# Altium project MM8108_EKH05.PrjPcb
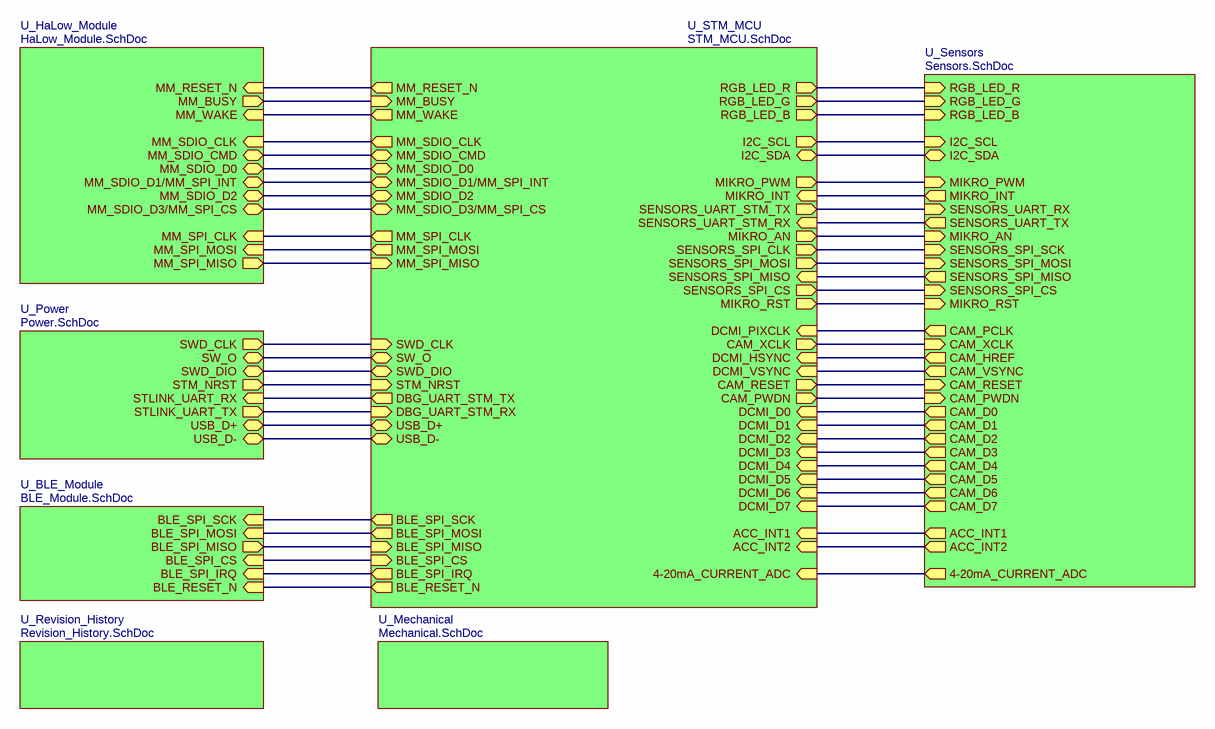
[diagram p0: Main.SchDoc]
PCBRev: 2.0; Rev: 2.1; DrawnBy: J. Garnier; Checked: Matthew Jay; Approved: Chad O'Neill
8 sheets, 188 parts. Net scope: hierarchical (ports join the sheet entries above them; power ports are global).
Board file: MM8108_EKH05.PcbDoc
Sheets:
  Main.SchDoc
    U_Power = Power.SchDoc
    U_STM_MCU = STM_MCU.SchDoc
    U_Sensors = Sensors.SchDoc
    U_BLE_Module = BLE_Module.SchDoc
    U_HaLow_Module = HaLow_Module.SchDoc
    U_Revision_History = Revision_History.SchDoc
    U_Mechanical = Mechanical.SchDoc

## Sheet Main.SchDoc: Top Level
size A4; ApprovedBy: Chad O'Neill; CheckedBy: Matthew Jay; Author: J. Garnier; DrawnBy: J. Garnier; Revision: 2.1; SheetNumber: 1; SheetTotal: 8

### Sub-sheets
U_BLE_Module = BLE_Module.SchDoc: BLE_RESET_N (in), BLE_SPI_IRQ (in), BLE_SPI_CS (in), BLE_SPI_SCK (in), BLE_SPI_MISO (out), BLE_SPI_MOSI (in)
U_HaLow_Module = HaLow_Module.SchDoc: MM_BUSY (out), MM_SDIO_D2 (bidir), MM_SDIO_D0 (bidir), MM_SDIO_CMD (bidir), MM_SDIO_CLK (in), MM_RESET_N (in), MM_WAKE (in), MM_SPI_MISO (out), MM_SPI_MOSI (in), MM_SPI_CLK (in), MM_SDIO_D1/MM_SPI_INT (bidir), MM_SDIO_D3/MM_SPI_CS (bidir)
U_Mechanical = Mechanical.SchDoc: no entries
U_Power = Power.SchDoc: SWD_CLK (out), SWD_DIO (bidir), STLINK_UART_RX (in), STLINK_UART_TX (out), STM_NRST (out), SW_O (bidir), USB_D+ (bidir), USB_D- (bidir)
U_Revision_History = Revision_History.SchDoc: no entries
U_Sensors = Sensors.SchDoc: ACC_INT1 (out), ACC_INT2 (out), RGB_LED_B (in), RGB_LED_G (in), RGB_LED_R (in), I2C_SCL (in), I2C_SDA (bidir), CAM_HREF (out), CAM_XCLK (in), CAM_D6 (out), CAM_D4 (out), CAM_D2 (out), CAM_D0 (out), CAM_D7 (out), CAM_D5 (out), CAM_D3 (out), CAM_D1 (out), CAM_PWDN (in), CAM_RESET (in), CAM_PCLK (out), CAM_VSYNC (out), MIKRO_INT (out), SENSORS_UART_RX (in), MIKRO_AN (in), SENSORS_SPI_CS (in), SENSORS_SPI_SCK (in), SENSORS_SPI_MISO (out), SENSORS_SPI_MOSI (in), SENSORS_UART_TX (out), MIKRO_PWM (in), MIKRO_RST (in), 4-20mA_CURRENT_ADC (out)
U_STM_MCU = STM_MCU.SchDoc: MM_RESET_N (out), SWD_DIO (bidir), SWD_CLK (in), SENSORS_SPI_MOSI (out), RGB_LED_G (out), RGB_LED_R (out), MM_SPI_CLK (out), RGB_LED_B (out), MM_SDIO_D0 (bidir), MM_BUSY (in), MM_SPI_MISO (in), MM_SPI_MOSI (out), MM_SDIO_CLK (out), MM_SDIO_CMD (bidir), MM_SDIO_D2 (bidir), DCMI_D5 (in), I2C_SCL (out), I2C_SDA (bidir), DCMI_D4 (in), DCMI_D6 (in), DCMI_D7 (in), DCMI_D3 (in), DCMI_D2 (in), DCMI_D1 (in), DCMI_D0 (in), DCMI_PIXCLK (in), DCMI_HSYNC (in), CAM_RESET (out), CAM_PWDN (out), ACC_INT1 (in), ACC_INT2 (in), DBG_UART_STM_RX (in), DBG_UART_STM_TX (out), BLE_RESET_N (out), SENSORS_UART_STM_RX (in), SENSORS_UART_STM_TX (out), DCMI_VSYNC (in), MM_WAKE (out), CAM_XCLK (out), SENSORS_SPI_MISO (in), SENSORS_SPI_CLK (out), SENSORS_SPI_CS (out), MIKRO_INT (in), MIKRO_AN (out), MIKRO_PWM (out), MIKRO_RST (out), 4-20mA_CURRENT_ADC (in), STM_NRST (in), SW_O (bidir), USB_D+ (bidir), USB_D- (bidir), MM_SDIO_D1/MM_SPI_INT (bidir), MM_SDIO_D3/MM_SPI_CS (bidir), BLE_SPI_SCK (out), BLE_SPI_CS (in), BLE_SPI_IRQ (out), BLE_SPI_MISO (in), BLE_SPI_MOSI (out)

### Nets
ACC_INT1: sheet U_STM_MCU/ACC_INT1, sheet U_Sensors/ACC_INT1
ACC_INT2: sheet U_STM_MCU/ACC_INT2, sheet U_Sensors/ACC_INT2
BLE_RESET_N: sheet U_STM_MCU/BLE_RESET_N, sheet U_BLE_Module/BLE_RESET_N
BLE_SPI_CS: sheet U_STM_MCU/BLE_SPI_CS, sheet U_BLE_Module/BLE_SPI_CS
BLE_SPI_IRQ: sheet U_STM_MCU/BLE_SPI_IRQ, sheet U_BLE_Module/BLE_SPI_IRQ
BLE_SPI_MISO: sheet U_STM_MCU/BLE_SPI_MISO, sheet U_BLE_Module/BLE_SPI_MISO
BLE_SPI_MOSI: sheet U_STM_MCU/BLE_SPI_MOSI, sheet U_BLE_Module/BLE_SPI_MOSI
BLE_SPI_SCK: sheet U_STM_MCU/BLE_SPI_SCK, sheet U_BLE_Module/BLE_SPI_SCK
CAM_PWDN: sheet U_STM_MCU/CAM_PWDN, sheet U_Sensors/CAM_PWDN
CAM_RESET: sheet U_STM_MCU/CAM_RESET, sheet U_Sensors/CAM_RESET
CAM_XCLK: sheet U_STM_MCU/CAM_XCLK, sheet U_Sensors/CAM_XCLK
DBG_UART_STM_RX: sheet U_Power/STLINK_UART_TX, sheet U_STM_MCU/DBG_UART_STM_RX
DBG_UART_STM_TX: sheet U_Power/STLINK_UART_RX, sheet U_STM_MCU/DBG_UART_STM_TX
DCMI_D0: sheet U_STM_MCU/DCMI_D0, sheet U_Sensors/CAM_D0
DCMI_D1: sheet U_STM_MCU/DCMI_D1, sheet U_Sensors/CAM_D1
DCMI_D2: sheet U_STM_MCU/DCMI_D2, sheet U_Sensors/CAM_D2
DCMI_D3: sheet U_STM_MCU/DCMI_D3, sheet U_Sensors/CAM_D3
DCMI_D4: sheet U_STM_MCU/DCMI_D4, sheet U_Sensors/CAM_D4
DCMI_D5: sheet U_STM_MCU/DCMI_D5, sheet U_Sensors/CAM_D5
DCMI_D6: sheet U_STM_MCU/DCMI_D6, sheet U_Sensors/CAM_D6
DCMI_D7: sheet U_STM_MCU/DCMI_D7, sheet U_Sensors/CAM_D7
DCMI_HSYNC: sheet U_STM_MCU/DCMI_HSYNC, sheet U_Sensors/CAM_HREF
DCMI_PIXCLK: sheet U_STM_MCU/DCMI_PIXCLK, sheet U_Sensors/CAM_PCLK
DCMI_VSYNC: sheet U_STM_MCU/DCMI_VSYNC, sheet U_Sensors/CAM_VSYNC
I2C_SCL: sheet U_STM_MCU/I2C_SCL, sheet U_Sensors/I2C_SCL
I2C_SDA: sheet U_STM_MCU/I2C_SDA, sheet U_Sensors/I2C_SDA
MIKRO_AN: sheet U_STM_MCU/MIKRO_AN, sheet U_Sensors/MIKRO_AN
MIKRO_INT: sheet U_STM_MCU/MIKRO_INT, sheet U_Sensors/MIKRO_INT
MIKRO_PWM: sheet U_STM_MCU/MIKRO_PWM, sheet U_Sensors/MIKRO_PWM
MIKRO_RST: sheet U_STM_MCU/MIKRO_RST, sheet U_Sensors/MIKRO_RST
MM_BUSY: sheet U_STM_MCU/MM_BUSY, sheet U_HaLow_Module/MM_BUSY
MM_RESET_N: sheet U_STM_MCU/MM_RESET_N, sheet U_HaLow_Module/MM_RESET_N
MM_SDIO_D1: sheet U_STM_MCU/MM_SDIO_D1/MM_SPI_INT, sheet U_HaLow_Module/MM_SDIO_D1/MM_SPI_INT
MM_SDIO_D2: sheet U_STM_MCU/MM_SDIO_D2, sheet U_HaLow_Module/MM_SDIO_D2
MM_SDIO_D3: sheet U_STM_MCU/MM_SDIO_D3/MM_SPI_CS, sheet U_HaLow_Module/MM_SDIO_D3/MM_SPI_CS
MM_WAKE: sheet U_STM_MCU/MM_WAKE, sheet U_HaLow_Module/MM_WAKE
PD11: sheet U_STM_MCU/4-20mA_CURRENT_ADC, sheet U_Sensors/4-20mA_CURRENT_ADC
SDMMC2_CLK: sheet U_STM_MCU/MM_SDIO_CLK, sheet U_HaLow_Module/MM_SDIO_CLK
SDMMC2_CMD: sheet U_STM_MCU/MM_SDIO_CMD, sheet U_HaLow_Module/MM_SDIO_CMD
SDMMC2_D0: sheet U_STM_MCU/MM_SDIO_D0, sheet U_HaLow_Module/MM_SDIO_D0
SENSORS_SPI_CLK: sheet U_STM_MCU/SENSORS_SPI_CLK, sheet U_Sensors/SENSORS_SPI_SCK
SENSORS_SPI_CS: sheet U_STM_MCU/SENSORS_SPI_CS, sheet U_Sensors/SENSORS_SPI_CS
SENSORS_SPI_MISO: sheet U_STM_MCU/SENSORS_SPI_MISO, sheet U_Sensors/SENSORS_SPI_MISO
SENSORS_SPI_MOSI: sheet U_STM_MCU/SENSORS_SPI_MOSI, sheet U_Sensors/SENSORS_SPI_MOSI
SENSORS_UART_RX: sheet U_STM_MCU/SENSORS_UART_STM_TX, sheet U_Sensors/SENSORS_UART_RX
SENSORS_UART_TX: sheet U_STM_MCU/SENSORS_UART_STM_RX, sheet U_Sensors/SENSORS_UART_TX
STM_NRST: sheet U_Power/STM_NRST, sheet U_STM_MCU/STM_NRST
STM_SPI2_CLK: sheet U_STM_MCU/MM_SPI_CLK, sheet U_HaLow_Module/MM_SPI_CLK
STM_SPI2_MISO: sheet U_STM_MCU/MM_SPI_MISO, sheet U_HaLow_Module/MM_SPI_MISO
STM_SPI2_MOSI: sheet U_STM_MCU/MM_SPI_MOSI, sheet U_HaLow_Module/MM_SPI_MOSI
SWD_CLK: sheet U_Power/SWD_CLK, sheet U_STM_MCU/SWD_CLK
SWD_DIO: sheet U_Power/SWD_DIO, sheet U_STM_MCU/SWD_DIO
TIM4_CH1: sheet U_STM_MCU/RGB_LED_R, sheet U_Sensors/RGB_LED_R
TIM4_CH2: sheet U_STM_MCU/RGB_LED_G, sheet U_Sensors/RGB_LED_G
TIM4_CH3: sheet U_STM_MCU/RGB_LED_B, sheet U_Sensors/RGB_LED_B
USBC_N: sheet U_Power/USB_D-, sheet U_STM_MCU/USB_D-
USBC_P: sheet U_Power/USB_D+, sheet U_STM_MCU/USB_D+
NetH16_5: sheet U_Power/SW_O, sheet U_STM_MCU/SW_O

## Sheet Power.SchDoc: Power
size A3; ApprovedBy: Chad O'Neill; CheckedBy: Matthew Jay; Author: J. Garnier; DrawnBy: J. Garnier; Revision: 2.1; SheetNumber: 6; SheetTotal: 8
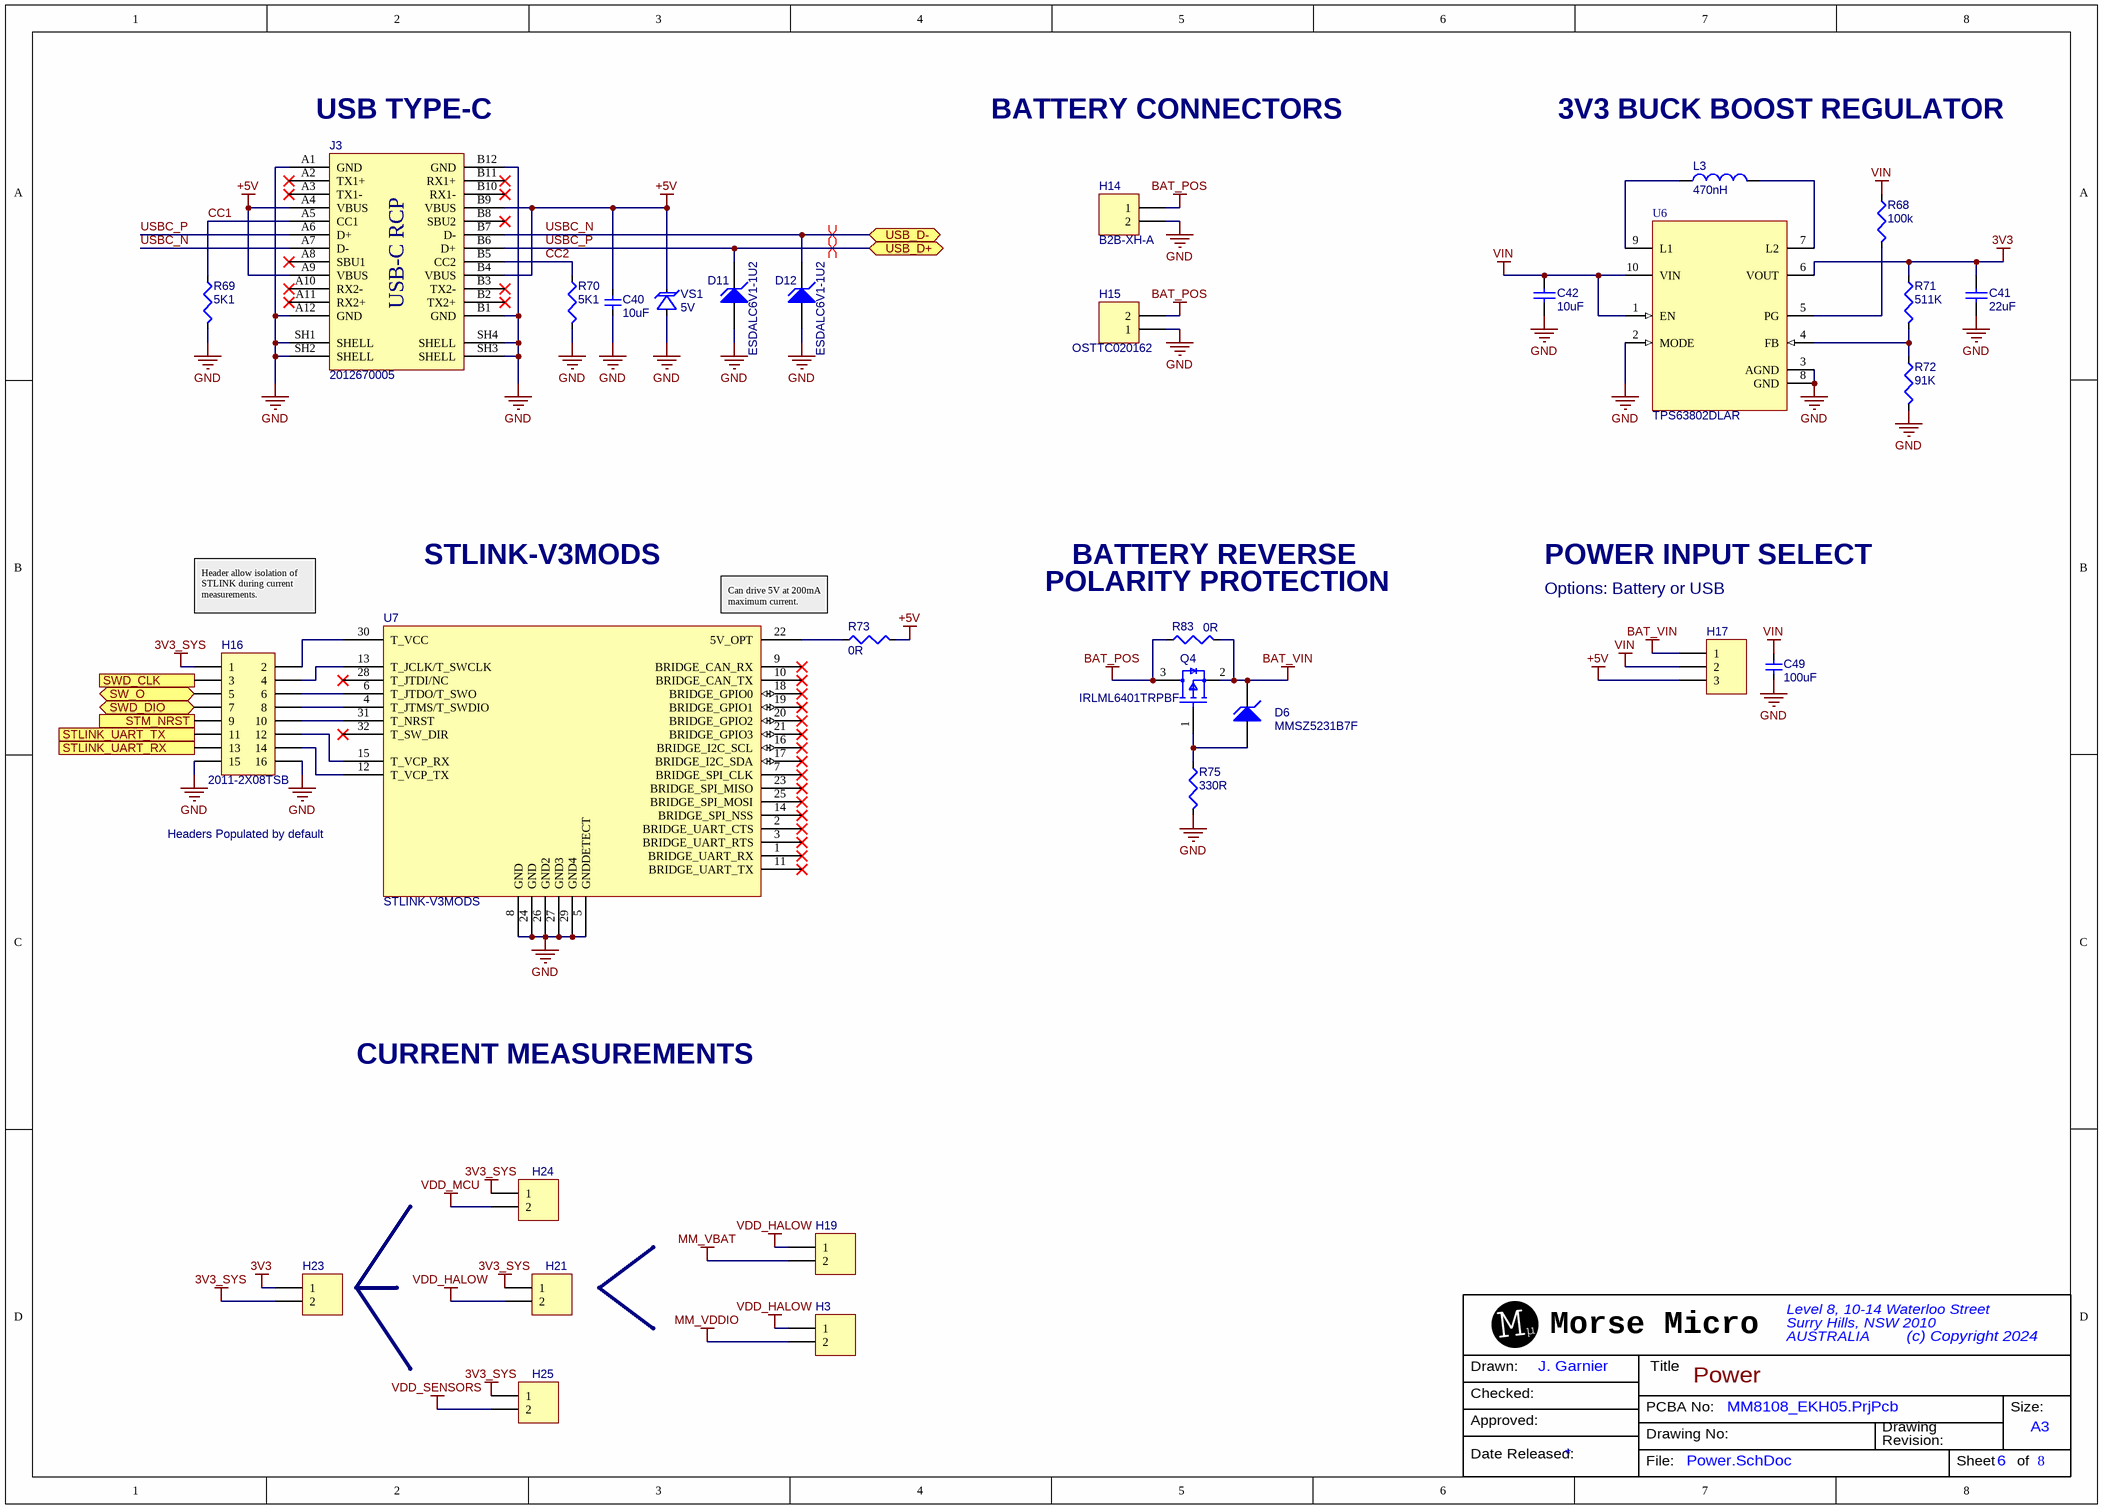
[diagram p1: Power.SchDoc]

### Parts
C40  value 10uF  [CAPC1608X06N]  (hidden comment: GRM188R61E106MA73J)
C41  value 22uF  [0603_cap]  (hidden comment: GRM188R60J226MEA0D)
C42  value 10uF  [0603_cap]  (hidden comment: GRM155R60J106ME05)
C49  value 100uF  [CAPC3225X20N]  (hidden comment: CL32A107MPVNNNE)
D6  MMSZ5231B7F  [SOD-123FL]
D11  ESDALC6V1-1U2  [0201_DIODE]
D12  ESDALC6V1-1U2  [0201_DIODE]
H3  2011-1X02G00SB-1  [HDR1X2]  (value not drawn)
H14  B2B-XH-A  [B2B-XH-A]
H15  OSTTC020162  [SCREW_TERM_2WAY_5MM]
H16  2011-2X08TSB  [HDR2X8 Short Gold]
H17  2011-1X03G00SB  [HDR1X3]  (value not drawn)
H19  2011-1X02G00SB-1  [HDR1X2]  (value not drawn)
H21  2011-1X02G00SB-1  [HDR1X2]  (value not drawn)
H23  2011-1X02G00SB-1  [HDR1X2]  (value not drawn)
H24  2011-1X02G00SB-1  [HDR1X2]  (value not drawn)
H25  2011-1X02G00SB-1  [HDR1X2]  (value not drawn)
J3  2012670005  [USB-C_RCP]
L3  value 470nH  [INDC2520X120N]  (hidden comment: DFE252012PR47MP2)
Q4  IRLML6401TRPBF  [FP-SOT23-IPC_A]
R68  value 100k  [RESC1005X04N]  (hidden comment: RC0402FR-07100KL)
R69  value 5K1  [RESC1005X04N]  (hidden comment: MCR01MZPF5101)
R70  value 5K1  [RESC1005X04N]  (hidden comment: MCR01MZPF5101)
R71  value 511K  [0402_res]  (hidden comment: RES0262)
R72  value 91K  [0402_res]  (hidden comment: RES0263)
R73  value 0R  [RESC1608X06N]  (hidden comment: RC0603JR-070RL)
R75  value 330R  [RESC1005X04N]  (hidden comment: RC0402FR-07330RL)
R83  value 0R  [RESC1608X06N]  (hidden comment: RC0603JR-070RL)
U6  TPS63802DLAR  [TPS63802DLAR]
U7  STLINK-V3MODS  [STLINK-V3MODS]
VS1  value 5V  [SOD-523]  (hidden comment: ESD5Z5.0T1G)

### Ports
STLINK_UART_RX (in, see Main[2B]), STLINK_UART_TX (out, see Main[2B]), STM_NRST (out, see Main[2B], STM_MCU[1B]), SW_O (bidir, see Main[2B], STM_MCU[4C]), SWD_CLK (out, see Main[2B], STM_MCU[5B]), SWD_DIO (bidir, see Main[2B], STM_MCU[5B]), USB_D+ (bidir, see Main[2B], STM_MCU[5B]), USB_D- (bidir, see Main[2B], STM_MCU[5B])

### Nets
3V3: C41.2 H23.1 R71.1 U6.6(VOUT)
3V3_SYS: H16.1 H21.1 H23.2 H24.1 H25.1
+5V: C40.1 H17.3 J3.A4(VBUS) J3.A9(VBUS) J3.B4(VBUS) J3.B9(VBUS) R73.2 VS1.K
BAT_POS: H14.1 H15.2 Q4.3(D) R83.1
BAT_VIN: D6.K H17.1 Q4.2(S) R83.2
GND: C40.2 C41.1 C42.1 C49.2 D11.A D12.A H14.2 H15.1 H16.15 H16.16 J3.A1(GND) J3.A12(GND) J3.B1(GND) J3.B12(GND) J3.SH1(SHELL) J3.SH2(SHELL) J3.SH3(SHELL) J3.SH4(SHELL) R69.2 R70.2 R72.2 R75.2 U6.2(MODE) U6.3(AGND) U6.8(GND) U7.5(GNDDETECT) U7.8(GND) U7.24(GND) U7.26(GND2) U7.27(GND3) U7.29(GND4) VS1.A
MM_VBAT: H19.2
MM_VDDIO: H3.2
VDD_HALOW: H3.1 H19.1 H21.2
VDD_MCU: H24.2
VDD_SENSORS: H25.2
VIN: C42.2 C49.1 H17.2 R68.1 U6.1(EN) U6.10(VIN)
CC1: J3.A5(CC1) R69.1
CC2: J3.B5(CC2) R70.1
DBG_UART_STM_RX: H16.11 ; port STLINK_UART_TX
DBG_UART_STM_TX: H16.13 ; port STLINK_UART_RX
STM_NRST: H16.9 ; port STM_NRST
SWD_CLK: H16.3 ; port SWD_CLK
SWD_DIO: H16.7 ; port SWD_DIO
USBC_N: D12.K J3.A7(D-) J3.B7(D-) ; port USB_D-
USBC_P: D11.K J3.A6(D+) J3.B6(D+) ; port USB_D+
NetD6_A: D6.A Q4.1(G) R75.1
NetH16_2: H16.2 U7.30(T_VCC)
NetH16_4: H16.4 U7.13(T_JCLK/T_SWCLK)
NetH16_5: H16.5 ; port SW_O
NetH16_6: H16.6 U7.6(T_JTDO/T_SWO)
NetH16_8: H16.8 U7.4(T_JTMS/T_SWDIO)
NetH16_10: H16.10 U7.31(T_NRST)
NetH16_12: H16.12 U7.15(T_VCP_RX)
NetH16_14: H16.14 U7.12(T_VCP_TX)
NetL3_1: L3.1 U6.9(L1)
NetL3_2: L3.2 U6.7(L2)
NetR68_2: R68.2 U6.5(PG)
NetR71_2: R71.2 R72.1 U6.4(FB)
NetR73_1: R73.1 U7.22(5V_OPT)

Not connected (* = marked no-connect by the designer): J3 A2(TX1+)* A3(TX1-)* A8(SBU1)* A10(RX2-)* A11(RX2+)* B2(TX2+)* B3(TX2-)* B8(SBU2)* B10(RX1-)* B11(RX1+)*; U7 1(BRIDGE_UART_RX)* 2(BRIDGE_UART_CTS)* 3(BRIDGE_UART_RTS)* 7(BRIDGE_SPI_CLK)* 9(BRIDGE_CAN_RX)* 10(BRIDGE_CAN_TX)* 11(BRIDGE_UART_TX)* 14(BRIDGE_SPI_NSS)* 16(BRIDGE_I2C_SCL)* 17(BRIDGE_I2C_SDA)* 18(BRIDGE_GPIO0)* 19(BRIDGE_GPIO1)* 20(BRIDGE_GPIO2)* 21(BRIDGE_GPIO3)* 23(BRIDGE_SPI_MISO)* 25(BRIDGE_SPI_MOSI)* 28(T_JTDI/NC)* 32(T_SW_DIR)*

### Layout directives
differential pair: USBC_N, USBC_P

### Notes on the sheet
- (near J3) USB TYPE-C
- BATTERY CONNECTORS
- 3V3 BUCK BOOST REGULATOR
- STLINK-V3MODS
- BATTERY REVERSE
- POWER INPUT SELECT
- Header allow isolation of STLINK during current measurements.
- Can drive 5V at 200mA maximum current.
- (near R83) POLARITY PROTECTION
- Options: Battery or USB
- Headers Populated by default
- CURRENT MEASUREMENTS

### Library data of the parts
C40 = CAP0197-5: CAP CER 10UF 25V ±20% X5R 0603; Generic Allowed: Yes; Subtype: Ceramic
C41 = CAP0243-1: Multilayer Ceramic Capacitor, 22 uF, 6.3 V, ± 20%, X5R, 0603 [1608 Metric]; Voltage Rating (DC): 6.3V
C42 = CAP0246-2: Ceramic Capacitor, Multilayer, Ceramic, 6.3V, 20% +Tol, 20% -Tol, X5R, 15% TC, 10uF, Surface Mount, 0402
C49 = CAP0047-3: CAP CER 100UF 10V ±20% X5R 1210; Generic Allowed: Yes; Subtype: Ceramic
D6 = DIO0072-1: DIODE ZENER 5.1V 500MW SOD-123
D11 D12 = DIO0043-4: TVS DIODE 3VWM ST020; Power: 20W; Generic Allowed: No; Voltage: 3V
H3 H19 H21 H23-H25 = HDR0006-2: Conn Straight Header 2x1 0.100" 2 POS; Generic Allowed: Yes
H14 = HDR0117-1: Board Connector, 2 Contact(s), 1 Row(s), Male, Straight, Solder Terminal,
H15 = JCK0020-1: CONN TERM BLOCK 5MM 2POS; Generic Allowed: Yes
H16 = HDR0116-2
H17 = HDR0008-2: Conn Straight Header 3x1 0.100" 3 POS; Generic Allowed: Yes
J3 = JCK0027-1: CONN RCP USB3.1 TYPEC 24P SMD RA; Generic Allowed: Yes
L3 = IND0139-3: Generic Allowed: NO; Current: 4; DC Resistance: 27mOhm
Q4 = TSR0020-1: Small Signal Field-Effect Transistor; Transistor Element Material: SILICON; Drain-source On Resistance-Max: 50mR; Power Dissipation-Max (Abs): 1.3W; Drain Current-Max (Abs) (ID): 4.3A; Polarity/Channel Type: P-CHANNEL; Number of Elements: 1; DS Breakdown Voltage-Min: 12V; Transistor Application: SWITCHING; FET Technology: METAL-OXIDE SEMICONDUCTOR; Qualification Status: Not Qualified; Additional Feature: HIGH RELIABILITY; Operating Mode: ENHANCEMENT MODE; Avalanche Energy Rating (Eas): 33mJ; Pulsed Drain Current-Max (IDM): 34A; Package Body Material: Plastic; Time @ Peak Reflow Temperature-Max (s): 30s
R68 = RES0044-8: RES SMD 100K OHM ±1% 1/16W 0402; Generic Allowed: Yes
R69 R70 = RES0094-8: RES SMD 5K1 OHM ±1% 1/16W 0402; Generic Allowed: Yes
R71 = RES0254-2: RES 511K OHM 1% 1/16W 0402; Manufacturer 1: YAGEO; Manufacturer Part Number 1: RC0402FR-07511KL; Subtype: Thick Film; Generic Allowed: Yes
R72 = RES0255-2: RES 91K OHM 1% 1/16W 0402; Manufacturer Part Number 1: RC0402FR-0791KL; Manufacturer 1: YAGEO; Generic Allowed: Yes; Subtype: Thick Film
R73 R83 = RES0119-6: RES SMD 0R OHM ±5% 1/10W 0603; Generic Allowed: Yes
R75 = RES0025-8: RES SMD 330R OHM ±1% 1/16W 0402; Generic Allowed: Yes
U6 = ICT0222-6: Generic Allowed: No
U7 = MOD0018-3
VS1 = DIO0073-1: TVS Diode,5V@9.4Amp, SOD-523 SMD; Current: 9.4A

## Sheet STM_MCU.SchDoc: STM_MCU
size A3; ApprovedBy: Chad O'Neill; CheckedBy: Matthew Jay; Author: J. Garnier; DrawnBy: J. Garnier; Revision: 2.1; SheetNumber: 2; SheetTotal: 8
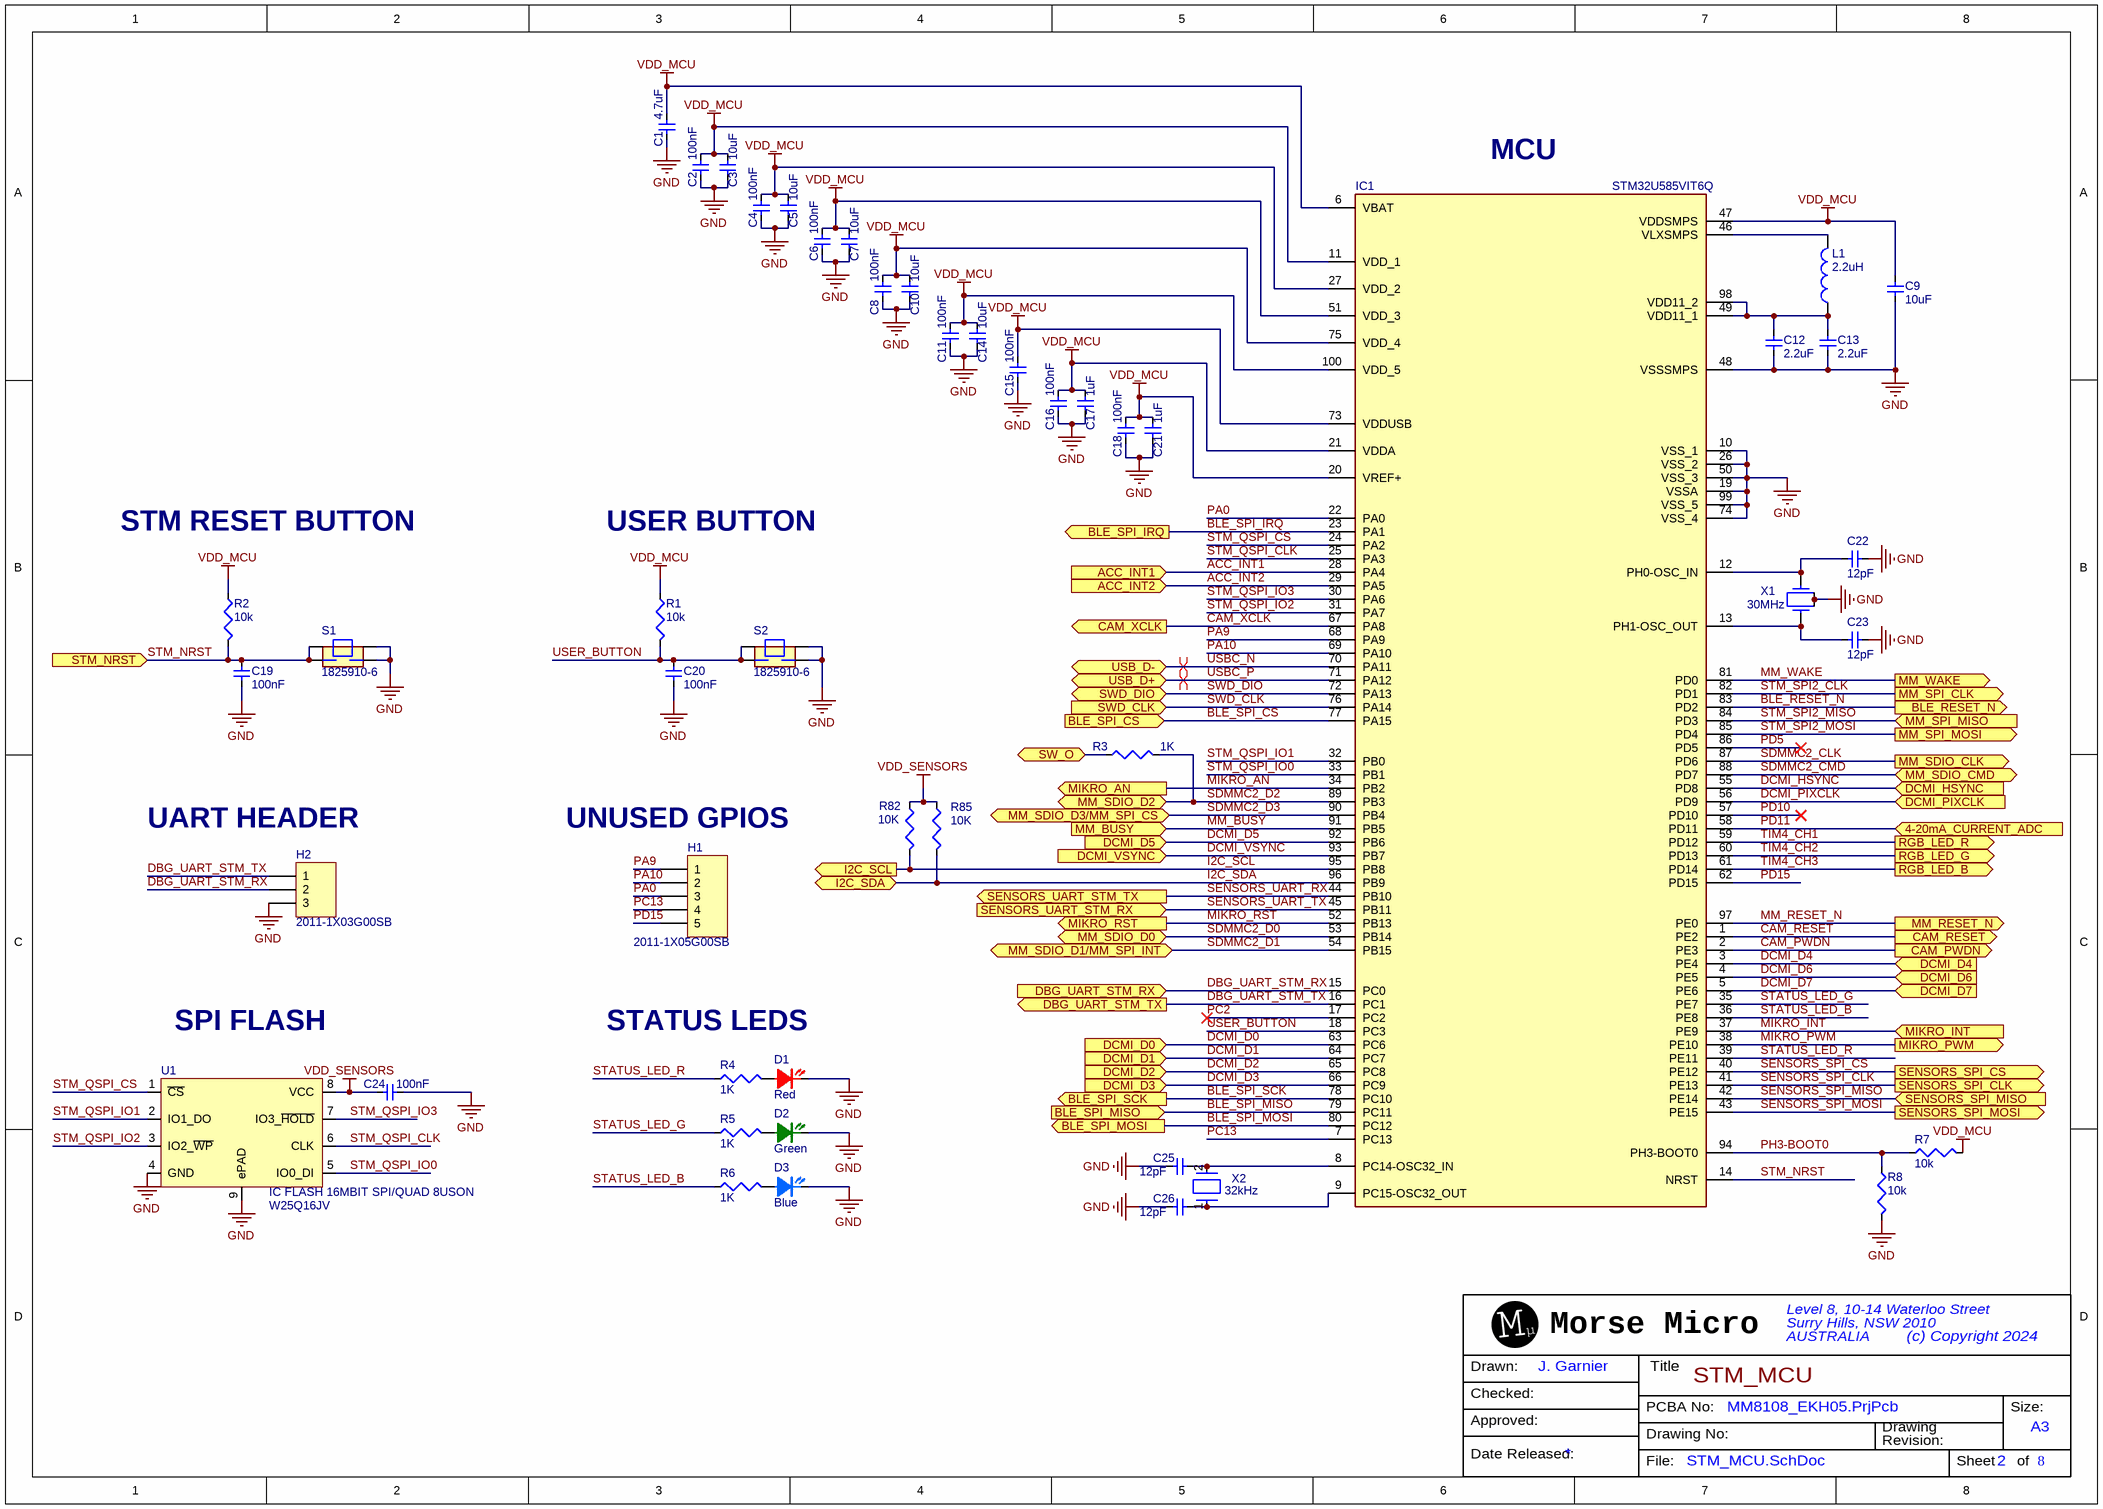
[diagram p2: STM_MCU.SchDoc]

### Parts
C1  value 4.7uF  [0402_cap]  (hidden comment: GRM155R61A475MEAAD)
C2  value 100nF  [0402_cap]  (hidden comment: C1005X7R1H104K050BE)
C3  value 10uF  [0402_cap]  (hidden comment: CL05A106MP8NUB8)
C4  value 100nF  [0402_cap]  (hidden comment: C1005X7R1H104K050BE)
C5  value 10uF  [0402_cap]  (hidden comment: CL05A106MP8NUB8)
C6  value 100nF  [0402_cap]  (hidden comment: C1005X7R1H104K050BE)
C7  value 10uF  [0402_cap]  (hidden comment: CL05A106MP8NUB8)
C8  value 100nF  [0402_cap]  (hidden comment: C1005X7R1H104K050BE)
C9  value 10uF  [0402_cap]  (hidden comment: CL05A106MP8NUB8)
C10  value 10uF  [0402_cap]  (hidden comment: CL05A106MP8NUB8)
C11  value 100nF  [0402_cap]  (hidden comment: C1005X7R1H104K050BE)
C12  value 2.2uF  [CAPC1005X06N]  (hidden comment: GRM155R61E225ME15D)
C13  value 2.2uF  [CAPC1005X06N]  (hidden comment: GRM155R61E225ME15D)
C14  value 10uF  [0402_cap]  (hidden comment: CL05A106MP8NUB8)
C15  value 100nF  [0402_cap]  (hidden comment: C1005X7R1H104K050BE)
C16  value 100nF  [0402_cap]  (hidden comment: C1005X7R1H104K050BE)
C17  value 1uF  [CAPC1005X06N]  (hidden comment: CL05A105KA5NQNC)
C18  value 100nF  [0402_cap]  (hidden comment: C1005X7R1H104K050BE)
C19  value 100nF  [CAPC1005X06N]  (hidden comment: LMK105BJ104KV-F)
C20  value 100nF  [CAPC1005X06N]  (hidden comment: LMK105BJ104KV-F)
C21  value 1uF  [CAPC1005X06N]  (hidden comment: CL05A105KA5NQNC)
C22  value 12pF  [CAPC0603X03N]  (hidden comment: GRM0335C1E120JA01D)
C23  value 12pF  [CAPC0603X03N]  (hidden comment: GRM0335C1E120JA01D)
C24  value 100nF  [CAPC0603X03N]  (hidden comment: CL03A104KQ3NNNC)
C25  value 12pF  [CAPC0603X03N]  (hidden comment: GRM0335C1E120JA01D)
C26  value 12pF  [CAPC0603X03N]  (hidden comment: GRM0335C1E120JA01D)
D1  value Red  [LED_0805_RED]  (hidden comment: LTST-C170KRKT)
D2  value Green  [LED_0805_GREEN]  (hidden comment: LTST-C170KGKT)
D3  value Blue  [LED_0805_BLUE]  (hidden comment: LTST-C170TBKT)
H1  2011-1X05G00SB  [HDR1X5 - Short Gold]
H2  2011-1X03G00SB  [HDR1X3]
IC1  STM32U585VIT6Q  [STM32U585VIT6]
L1  value 2.2uH  [INDC1608X10N]  (hidden comment: ASMPH-0603-2R2M-T)
R1  value 10k  [RESC1005X04N]  (hidden comment: MCR01MZPF1002)
R2  value 10k  [RESC1005X04N]  (hidden comment: MCR01MZPF1002)
R3  value 1K  [RESC1005X04N]  (hidden comment: ERJ-2RKF1001X)
R4  value 1K  [RESC1005X04N]  (hidden comment: ERJ-2RKF1001X)
R5  value 1K  [RESC1005X04N]  (hidden comment: ERJ-2RKF1001X)
R6  value 1K  [RESC1005X04N]  (hidden comment: ERJ-2RKF1001X)
R7  value 10k  [RESC1005X04N]  (hidden comment: MCR01MZPF1002)
R8  value 10k  [RESC1005X04N]  (hidden comment: MCR01MZPF1002)
R82  value 10K  [0402_res]  (hidden comment: ERJ-2RKF1002X)
R85  value 10K  [0402_res]  (hidden comment: ERJ-2RKF1002X)
S1  1825910-6  [TL1105]
S2  1825910-6  [TL1105]
U1  IC FLASH 16MBIT SPI/QUAD 8USON  value W25Q16JV  [USON8P20X30X6]
X1  value 30MHz  [XTAL_SMD_2016]  (hidden comment: ECS-300-10-37-CKM-TR)
X2  value 32kHz  [FP-ABS06-MFG]  (hidden comment: ABS06-107-32.768KHZ-T)

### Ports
4-20mA_CURRENT_ADC (in, see Main[3C], Sensors[7A]), ACC_INT1 (in, see Main[3C], Sensors[1D]), ACC_INT2 (in, see Main[3C], Sensors[1D]), BLE_RESET_N (out, see Main[2C], BLE_Module[2B]), BLE_SPI_CS (in, see Main[2C], BLE_Module[4B]), BLE_SPI_IRQ (out, see Main[2C], BLE_Module[4B]), BLE_SPI_MISO (in, see Main[2C], BLE_Module[4B]), BLE_SPI_MOSI (out, see Main[2C], BLE_Module[4B]), BLE_SPI_SCK (out, see Main[2C], BLE_Module[4A]), CAM_PWDN (out, see Main[3B], Sensors[7B]), CAM_RESET (out, see Main[3B], Sensors[5B]), CAM_XCLK (out, see Main[3B], Sensors[7B]), DBG_UART_STM_RX (in, see Main[2B]), DBG_UART_STM_TX (out, see Main[2B]), DCMI_D0 (in, see Main[3B]), DCMI_D1 (in, see Main[3B]), DCMI_D2 (in, see Main[3B]), DCMI_D3 (in, see Main[3C]), DCMI_D4 (in, see Main[3C]), DCMI_D5 (in, see Main[3C]), DCMI_D6 (in, see Main[3C]), DCMI_D7 (in, see Main[3C]), DCMI_HSYNC (in, see Main[3B]), DCMI_PIXCLK (in, see Main[3B]), DCMI_VSYNC (in, see Main[3B]), I2C_SCL (out, see Main[3A], Sensors[4A]), I2C_SDA (bidir, see Main[3A], Sensors[4A]), MIKRO_AN (out, see Main[3B], Sensors[2B]), MIKRO_INT (in, see Main[3B], Sensors[4B]), MIKRO_PWM (out, see Main[3A], Sensors[4B]), MIKRO_RST (out, see Main[3B], Sensors[2B]), MM_BUSY (in, see Main[2A], HaLow_Module[3A]), MM_RESET_N (out, see Main[2A], HaLow_Module[2B]), MM_SDIO_CLK (out, see Main[2A], HaLow_Module[2C]), MM_SDIO_CMD (bidir, see Main[2A], HaLow_Module[2C]), MM_SDIO_D0 (bidir, see Main[2A], HaLow_Module[2C]), MM_SDIO_D1/MM_SPI_INT (bidir, see Main[2A], HaLow_Module[1B]), MM_SDIO_D2 (bidir, see Main[2B], HaLow_Module[1B]), MM_SDIO_D3/MM_SPI_CS (bidir, see Main[2B], HaLow_Module[1B]), MM_SPI_CLK (out, see Main[2B], HaLow_Module[2C]), MM_SPI_MISO (in, see Main[2B], HaLow_Module[2C]), MM_SPI_MOSI (out, see Main[2B], HaLow_Module[2C]), MM_WAKE (out, see Main[2A], HaLow_Module[2B]), RGB_LED_B (out, see Main[3A], Sensors[4D]), RGB_LED_G (out, see Main[3A], Sensors[4D]), RGB_LED_R (out, see Main[3A], Sensors[5D]), SENSORS_SPI_CLK (out, see Main[3B]), SENSORS_SPI_CS (out, see Main[3B], Sensors[2B]), SENSORS_SPI_MISO (in, see Main[3B], Sensors[2B]), SENSORS_SPI_MOSI (out, see Main[3B], Sensors[2B]), SENSORS_UART_STM_RX (in, see Main[3B]), SENSORS_UART_STM_TX (out, see Main[3B]), STM_NRST (in, see Main[2B], Power[1B]), SW_O (bidir, see Main[2B], Power[1B]), SWD_CLK (in, see Main[2B], Power[1B]), SWD_DIO (bidir, see Main[2B], Power[1B]), USB_D+ (bidir, see Main[2B], Power[4A]), USB_D- (bidir, see Main[2B], Power[4A])

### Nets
GND: C1.1 C2.1 C3.1 C4.1 C5.1 C6.1 C7.1 C8.1 C9.2 C10.1 C11.1 C12.2 C13.2 C14.1 C15.1 C16.1 C17.1 C18.1 C19.2 C20.2 C21.1 C22.2 C23.2 C24.1 C25.1 C26.1 D1.K D2.K D3.K H2.3 IC1.10(VSS_1) IC1.19(VSSA) IC1.26(VSS_2) IC1.48(VSSSMPS) IC1.50(VSS_3) IC1.74(VSS_4) IC1.99(VSS_5) R8.2 S1.3 S1.4 S2.3 S2.4 U1.4(GND) U1.9(ePAD) X1.2 X1.4
VDD_MCU: C1.2 C2.2 C3.2 C4.2 C5.2 C6.2 C7.2 C8.2 C9.1 C10.2 C11.2 C14.2 C15.2 C16.2 C17.2 C18.2 C21.2 IC1.6(VBAT) IC1.11(VDD_1) IC1.20(VREF+) IC1.21(VDDA) IC1.27(VDD_2) IC1.47(VDDSMPS) IC1.51(VDD_3) IC1.73(VDDUSB) IC1.75(VDD_4) IC1.100(VDD_5) R1.1 R2.1 R7.2
VDD_SENSORS: C24.2 R82.1 R85.1 U1.8(VCC)
ACC_INT1: IC1.28(PA4) ; port ACC_INT1
ACC_INT2: IC1.29(PA5) ; port ACC_INT2
BLE_RESET_N: IC1.83(PD2) ; port BLE_RESET_N
BLE_SPI_CS: IC1.77(PA15) ; port BLE_SPI_CS
BLE_SPI_IRQ: IC1.23(PA1) ; port BLE_SPI_IRQ
BLE_SPI_MISO: IC1.79(PC11) ; port BLE_SPI_MISO
BLE_SPI_MOSI: IC1.80(PC12) ; port BLE_SPI_MOSI
BLE_SPI_SCK: IC1.78(PC10) ; port BLE_SPI_SCK
CAM_PWDN: IC1.2(PE3) ; port CAM_PWDN
CAM_RESET: IC1.1(PE2) ; port CAM_RESET
CAM_XCLK: IC1.67(PA8) ; port CAM_XCLK
DBG_UART_STM_RX: H2.2 IC1.15(PC0) ; port DBG_UART_STM_RX
DBG_UART_STM_TX: H2.1 IC1.16(PC1) ; port DBG_UART_STM_TX
DCMI_D0: IC1.63(PC6) ; port DCMI_D0
DCMI_D1: IC1.64(PC7) ; port DCMI_D1
DCMI_D2: IC1.65(PC8) ; port DCMI_D2
DCMI_D3: IC1.66(PC9) ; port DCMI_D3
DCMI_D4: IC1.3(PE4) ; port DCMI_D4
DCMI_D5: IC1.92(PB6) ; port DCMI_D5
DCMI_D6: IC1.4(PE5) ; port DCMI_D6
DCMI_D7: IC1.5(PE6) ; port DCMI_D7
DCMI_HSYNC: IC1.55(PD8) ; port DCMI_HSYNC
DCMI_PIXCLK: IC1.56(PD9) ; port DCMI_PIXCLK
DCMI_VSYNC: IC1.93(PB7) ; port DCMI_VSYNC
I2C_SCL: IC1.95(PB8) R82.2 ; port I2C_SCL
I2C_SDA: IC1.96(PB9) R85.2 ; port I2C_SDA
MIKRO_AN: IC1.34(PB2) ; port MIKRO_AN
MIKRO_INT: IC1.37(PE9) ; port MIKRO_INT
MIKRO_PWM: IC1.38(PE10) ; port MIKRO_PWM
MIKRO_RST: IC1.52(PB13) ; port MIKRO_RST
MM_BUSY: IC1.91(PB5) ; port MM_BUSY
MM_RESET_N: IC1.97(PE0) ; port MM_RESET_N
MM_WAKE: IC1.81(PD0) ; port MM_WAKE
PA0: H1.3 IC1.22(PA0)
PA9: H1.1 IC1.68(PA9)
PA10: H1.2 IC1.69(PA10)
PC2: IC1.17(PC2)
PC13: H1.4 IC1.7(PC13)
PD5: IC1.86(PD5)
PD10: IC1.57(PD10)
PD11: IC1.58(PD11) ; port 4-20mA_CURRENT_ADC
PD15: H1.5 IC1.62(PD15)
PH3-BOOT0: IC1.94(PH3-BOOT0) R7.1 R8.1
SDMMC2_CLK: IC1.87(PD6) ; port MM_SDIO_CLK
SDMMC2_CMD: IC1.88(PD7) ; port MM_SDIO_CMD
SDMMC2_D0: IC1.53(PB14) ; port MM_SDIO_D0
SDMMC2_D1: IC1.54(PB15) ; port MM_SDIO_D1/MM_SPI_INT  [project net MM_SDIO_D1]
SDMMC2_D2: IC1.89(PB3) R3.2 ; port MM_SDIO_D2  [project net MM_SDIO_D2]
SDMMC2_D3: IC1.90(PB4) ; port MM_SDIO_D3/MM_SPI_CS  [project net MM_SDIO_D3]
SENSORS_SPI_CLK: IC1.41(PE13) ; port SENSORS_SPI_CLK
SENSORS_SPI_CS: IC1.40(PE12) ; port SENSORS_SPI_CS
SENSORS_SPI_MISO: IC1.42(PE14) ; port SENSORS_SPI_MISO
SENSORS_SPI_MOSI: IC1.43(PE15) ; port SENSORS_SPI_MOSI
SENSORS_UART_RX: IC1.44(PB10) ; port SENSORS_UART_STM_TX
SENSORS_UART_TX: IC1.45(PB11) ; port SENSORS_UART_STM_RX
STATUS_LED_B: IC1.36(PE8) R6.1
STATUS_LED_G: IC1.35(PE7) R5.1
STATUS_LED_R: IC1.39(PE11) R4.1
STM_NRST: C19.1 IC1.14(NRST) R2.2 S1.1 S1.2 ; port STM_NRST
STM_QSPI_CLK: IC1.25(PA3) U1.6(CLK)
STM_QSPI_CS: IC1.24(PA2) U1.1(~{CS})
STM_QSPI_IO0: IC1.33(PB1) U1.5(IO0_DI)
STM_QSPI_IO1: IC1.32(PB0) U1.2(IO1_DO)
STM_QSPI_IO2: IC1.31(PA7) U1.3(IO2_~{WP})
STM_QSPI_IO3: IC1.30(PA6) U1.7(IO3_~{HOLD})
STM_SPI2_CLK: IC1.82(PD1) ; port MM_SPI_CLK
STM_SPI2_MISO: IC1.84(PD3) ; port MM_SPI_MISO
STM_SPI2_MOSI: IC1.85(PD4) ; port MM_SPI_MOSI
SWD_CLK: IC1.76(PA14) ; port SWD_CLK
SWD_DIO: IC1.72(PA13) ; port SWD_DIO
TIM4_CH1: IC1.59(PD12) ; port RGB_LED_R
TIM4_CH2: IC1.60(PD13) ; port RGB_LED_G
TIM4_CH3: IC1.61(PD14) ; port RGB_LED_B
USBC_N: IC1.70(PA11) ; port USB_D-
USBC_P: IC1.71(PA12) ; port USB_D+
USER_BUTTON: C20.1 IC1.18(PC3) R1.2 S2.1 S2.2
NetC12_1: C12.1 C13.1 IC1.49(VDD11_1) IC1.98(VDD11_2) L1.1
NetC22_1: C22.1 IC1.12(PH0-OSC_IN) X1.3
NetC23_1: C23.1 IC1.13(PH1-OSC_OUT) X1.1
NetC25_2: C25.2 IC1.8(PC14-OSC32_IN) X2.2
NetC26_2: C26.2 IC1.9(PC15-OSC32_OUT) X2.1
NetD1_A: D1.A R4.2
NetD2_A: D2.A R5.2
NetD3_A: D3.A R6.2
NetH16_5: R3.1 ; port SW_O
NetIC1_46: IC1.46(VLXSMPS) L1.2

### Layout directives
differential pair: USBC_N, USBC_P

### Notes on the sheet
- (near IC1) MCU
- STM RESET BUTTON
- USER BUTTON
- (near H2) UART HEADER
- (near H1) UNUSED GPIOS
- SPI FLASH
- STATUS LEDS

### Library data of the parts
C1 = CAP0157-11: CAP CER 4.7UF 10V ±20% X5R 0402; Subtype: Ceramic; Generic Allowed: Yes
C2 C4 C6 C8 C11 C15 C16 C18 = CAP0068-11: CAP CER 100NF 50V ±10% X7R 0402; Subtype: Ceramic; Generic Allowed: Yes
C3 C5 C7 C9 C10 C14 = CAP0046-13: CAP CER 10UF 10V 20% X5R 0402; Generic Allowed: Yes; Subtype: Ceramic
C12 C13 = CAP0055-10: CAP CER 2.2UF 25V ±20% X5R 0402; Subtype: Ceramic; Generic Allowed: Yes
C17 C21 = CAP0168-10: CAP CER 1UF 25V ±10% X5R 0402; Generic Allowed: Yes; Subtype: Ceramic
C19 C20 = CAP0196-10: CAP CER 100NF 10V ±10% X5R 0402; Generic Allowed: Yes; Subtype: Ceramic
C22 C23 C25 C26 = CAP0010-6: CAP CER 12PF 25V ±5% C0G/NP0 0201; Subtype: Ceramic; Generic Allowed: Yes; Component Rating: C0G, NPO
C24 = CAP0134-6: CAP CER 100NF 6.3V ±10% X5R 0201; Subtype: Ceramic; Generic Allowed: Yes
D1 = DIO0016-2: LED, Red Clear,2.0V, SMD, 0805, RoHS; Generic Allowed: Yes
D2 = DIO0015-2: LED, Green Clear,2.0V, SMD, 0805, RoHS; Generic Allowed: Yes
D3 = DIO0018-2: LED, Blue Clear,3.3V, SMD, 0805, RoHS; Generic Allowed: Yes
H1 = HDR0119-2: 2011 Series Single Row 5 Position 2.54 mm 3 A Straight Gold Flash Pin Header
H2 = HDR0008-2: as H17 on sheet Power
IC1 = ICT0224-2: Generic Allowed: No
L1 = IND0038-5: INDUCTOR 2.2UH 10% 0603 SMD; Generic Allowed: Yes; Tolerance: 20%; Current: 300mA; Resistance: 300mOhm; Frequency: 80MHz
R1 R2 R7 R8 = RES0043-8: RES SMD 10K OHM ±1% 1/16W 0402; Generic Allowed: Yes
R3-R6 = RES0004-8: RES SMD 1K OHM ±1% 1/10W 0402; Generic Allowed: Yes
R82 R85 = RES0002-9: RES SMD 10K OHM ±1% 1/10W 0402; Generic Allowed: Yes
S1 S2 = SWH0038-1: Keypad Switch, 1 Switches, SPST, Momentary-tactile, 0.05A, 24VDC, 2.06N, 4 PCB Hole Cnt, Solder Terminal, Through Hole-straight; Body Height: 3.61mm; Body Length or Diameter: 5.99mm; Body Breadth: 5.99inch; Contact DC Max Rating R Load: .05A@24VDC; Contact Current(DC)-Max: 50mA; Circuit Configuration: 1X1; Electrical Life: 100000Cycles; Number of Switches: 1; Contact Voltage(DC)-Max: 24V
U1 = ICT0220-1: Generic Allowed: No
X1 = OSC0002-3: OSC XTAL 30MHZ 10PF 10PPM SMD2016; Generic Allowed: No
X2 = OSC0044-1: Parallel - Fundamental Quartz Crystal, 0.032768MHz Nom; Frequency Stability: 0.025%; Additional Feature: TAPE AND REEL; Drive Level: 0.1uW; ESR: 80kR; Aging: 3 PPM/FIRST YEAR; Frequency Tolerance: 20ppm; Load Capacitance: 4pF

## Sheet Sensors.SchDoc: Sensors
size A3; ApprovedBy: Chad O'Neill; CheckedBy: Matthew Jay; Author: J. Garnier; DrawnBy: J. Garnier; Revision: 2.1; SheetNumber: 5; SheetTotal: 8
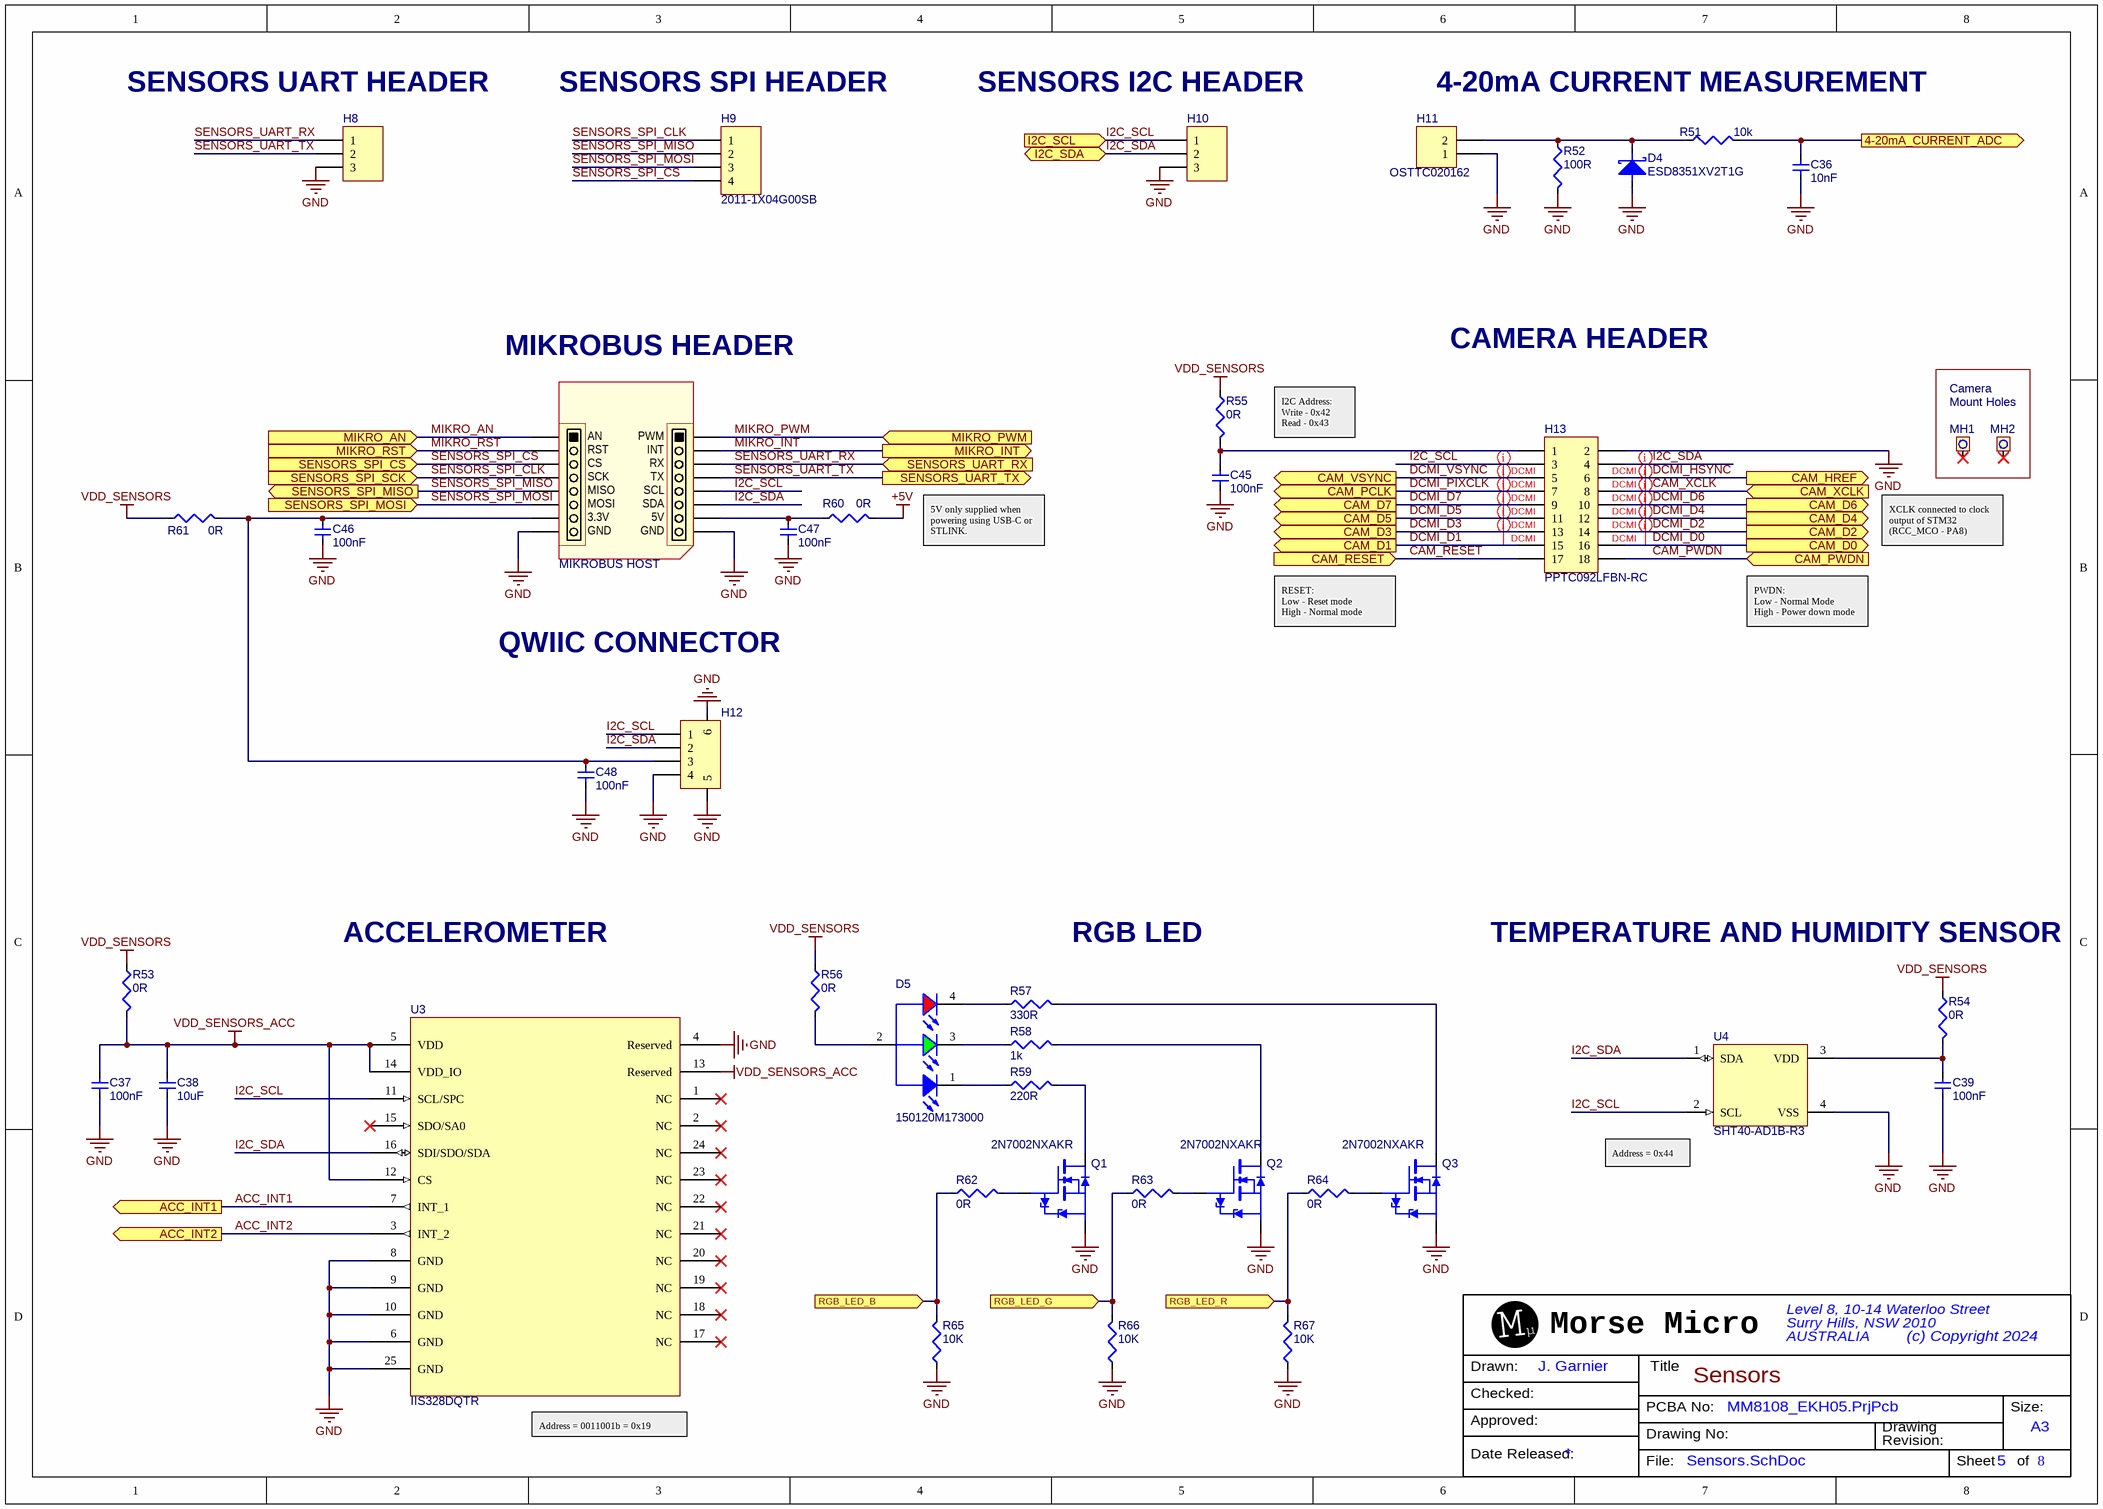
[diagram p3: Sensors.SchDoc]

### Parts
C36  value 10nF  [CAPC1005X06N]  (hidden comment: GRM155R71E103KA01D)
C37  value 100nF  [0402_cap]  (hidden comment: C1005X7R1H104K050BE)
C38  value 10uF  [0402_cap]  (hidden comment: CL05A106MP8NUB8)
C39  value 100nF  [0402_cap]  (hidden comment: C1005X7R1H104K050BE)
C45  value 100nF  [0402_cap]  (hidden comment: C1005X7R1H104K050BE)
C46  value 100nF  [0402_cap]  (hidden comment: C1005X7R1H104K050BE)
C47  value 100nF  [0402_cap]  (hidden comment: C1005X7R1H104K050BE)
C48  value 100nF  [0402_cap]  (hidden comment: C1005X7R1H104K050BE)
D4  ESD8351XV2T1G  [SOD-523-DIODE]
D5  150120M173000  [WL-SFCW_1206]
H8  2011-1X03G00SB  [HDR1X3]  (value not drawn)
H9  2011-1X04G00SB  [HDR1X4 - Short Gold]
H10  2011-1X03G00SB  [HDR1X3]  (value not drawn)
H11  OSTTC020162  [SCREW_TERM_2WAY_5MM]
H12  SM04B-SRSS-TBLFSN  [SM04B-SRSS-TB]  (value not drawn)
H13  PPTC092LFBN-RC  [HDR2X9 Female]
J1  75915-308GLF  [75915-308LF]  (value not drawn)
J2  75915-308GLF  [75915-308LF]  (value not drawn)
MH1  PAD0009  [MH_300_275_NPTH]  (value not drawn)
MH2  PAD0009  [MH_300_275_NPTH]  (value not drawn)
Q1  2N7002NXAKR  [SOT95P240X120_GSD-3N(SOT23-3L)]
Q2  2N7002NXAKR  [SOT95P240X120_GSD-3N(SOT23-3L)]
Q3  2N7002NXAKR  [SOT95P240X120_GSD-3N(SOT23-3L)]
R51  value 10k  [RESC1005X04N]  (hidden comment: MCR01MZPF1002)
R52  value 100R  [RESC1608X06N]  (hidden comment: RNCS0603BKE100R)
R53  value 0R  [RESC1608X06N]  (hidden comment: RC0603JR-070RL)
R54  value 0R  [RESC1608X06N]  (hidden comment: RC0603JR-070RL)
R55  value 0R  [RESC1608X06N]  (hidden comment: RC0603JR-070RL)
R56  value 0R  [RESC1608X06N]  (hidden comment: RC0603JR-070RL)
R57  value 330R  [0402_res]  (hidden comment: RC0402FR-07330RL)
R58  value 1k  [0402_res]  (hidden comment: RC0402FR-071KL)
R59  value 220R  [0402_res]  (hidden comment: MCR01MZPF2200)
R60  value 0R  [RESC1608X06N]  (hidden comment: RC0603JR-070RL)
R61  value 0R  [RESC1608X06N]  (hidden comment: RC0603JR-070RL)
R62  value 0R  [RESC1608X06N]  (hidden comment: RC0603JR-070RL)
R63  value 0R  [RESC1608X06N]  (hidden comment: RC0603JR-070RL)
R64  value 0R  [RESC1608X06N]  (hidden comment: RC0603JR-070RL)
R65  value 10K  [RESC1005X04N]  (hidden comment: ERJ-2RKF1002X)
R66  value 10K  [RESC1005X04N]  (hidden comment: ERJ-2RKF1002X)
R67  value 10K  [RESC1005X04N]  (hidden comment: ERJ-2RKF1002X)
U3  IIS328DQTR  [QFN50P400X400X185_HS-25N]
U4  SHT40-AD1B-R3  [DFN140P150X59-4N]
U5  MIKROBUS HOST  [MIKROBUS_Host_SD]  (no BOM)

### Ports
4-20mA_CURRENT_ADC (out, see Main[3C], STM_MCU[8C]), ACC_INT1 (out, see Main[3C], STM_MCU[5B]), ACC_INT2 (out, see Main[3C], STM_MCU[5B]), CAM_D0 (out, see Main[3B]), CAM_D1 (out, see Main[3B]), CAM_D2 (out, see Main[3B]), CAM_D3 (out, see Main[3C]), CAM_D4 (out, see Main[3C]), CAM_D5 (out, see Main[3C]), CAM_D6 (out, see Main[3C]), CAM_D7 (out, see Main[3C]), CAM_HREF (out, see Main[3B]), CAM_PCLK (out, see Main[3B]), CAM_PWDN (in, see Main[3B], STM_MCU[8C]), CAM_RESET (in, see Main[3B], STM_MCU[8C]), CAM_VSYNC (out, see Main[3B]), CAM_XCLK (in, see Main[3B], STM_MCU[5B]), I2C_SCL (in, see Main[3A], STM_MCU[4C]), I2C_SDA (bidir, see Main[3A], STM_MCU[4C]), MIKRO_AN (in, see Main[3B], STM_MCU[5C]), MIKRO_INT (out, see Main[3B], STM_MCU[8C]), MIKRO_PWM (in, see Main[3A], STM_MCU[8C]), MIKRO_RST (in, see Main[3B], STM_MCU[5C]), RGB_LED_B (in, see Main[3A], STM_MCU[8C]), RGB_LED_G (in, see Main[3A], STM_MCU[8C]), RGB_LED_R (in, see Main[3A], STM_MCU[8C]), SENSORS_SPI_CS (in, see Main[3B], STM_MCU[8C]), SENSORS_SPI_MISO (out, see Main[3B], STM_MCU[8C]), SENSORS_SPI_MOSI (in, see Main[3B], STM_MCU[8C]), SENSORS_SPI_SCK (in, see Main[3B]), SENSORS_UART_RX (in, see Main[3B]), SENSORS_UART_TX (out, see Main[3B])

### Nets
+5V: R60.2
GND: C36.2 C37.1 C38.1 C39.1 C45.1 C46.1 C47.1 C48.1 D4.A H8.3 H10.3 H11.1 H12.4 H12.5 H12.6 H13.2 J1.8 J2.8 Q1.S Q2.S Q3.S R52.2 R65.1 R66.1 R67.1 U3.4(Reserved) U3.6(GND) U3.8(GND) U3.9(GND) U3.10(GND) U3.25(GND) U4.4(VSS)
VDD_SENSORS: R53.1 R54.1 R55.1 R56.1 R61.1
VDD_SENSORS_ACC: C37.2 C38.2 R53.2 U3.5(VDD) U3.12(CS) U3.13(Reserved) U3.14(VDD_IO)
ACC_INT1: U3.7(INT_1) ; port ACC_INT1
ACC_INT2: U3.3(INT_2) ; port ACC_INT2
CAM_PWDN: H13.18 ; port CAM_PWDN
CAM_RESET: H13.17 ; port CAM_RESET
CAM_XCLK: H13.8 ; port CAM_XCLK
DCMI_D0: H13.16 ; port CAM_D0
DCMI_D1: H13.15 ; port CAM_D1
DCMI_D2: H13.14 ; port CAM_D2
DCMI_D3: H13.13 ; port CAM_D3
DCMI_D4: H13.12 ; port CAM_D4
DCMI_D5: H13.11 ; port CAM_D5
DCMI_D6: H13.10 ; port CAM_D6
DCMI_D7: H13.9 ; port CAM_D7
DCMI_HSYNC: H13.6 ; port CAM_HREF
DCMI_PIXCLK: H13.7 ; port CAM_PCLK
DCMI_VSYNC: H13.5 ; port CAM_VSYNC
I2C_SCL: H10.1 H12.1 H13.3 J2.5 U3.11(SCL/SPC) U4.2(SCL) ; port I2C_SCL
I2C_SDA: H10.2 H12.2 H13.4 J2.6 U3.16(SDI/SDO/SDA) U4.1(SDA) ; port I2C_SDA
MIKRO_AN: J1.1 ; port MIKRO_AN
MIKRO_INT: J2.2 ; port MIKRO_INT
MIKRO_PWM: J2.1 ; port MIKRO_PWM
MIKRO_RST: J1.2 ; port MIKRO_RST
PD11: C36.1 R51.2 ; port 4-20mA_CURRENT_ADC
SENSORS_SPI_CLK: H9.1 J1.4 ; port SENSORS_SPI_SCK
SENSORS_SPI_CS: H9.4 J1.3 ; port SENSORS_SPI_CS
SENSORS_SPI_MISO: H9.2 J1.5 ; port SENSORS_SPI_MISO
SENSORS_SPI_MOSI: H9.3 J1.6 ; port SENSORS_SPI_MOSI
SENSORS_UART_RX: H8.1 J2.3 ; port SENSORS_UART_RX
SENSORS_UART_TX: H8.2 J2.4 ; port SENSORS_UART_TX
TIM4_CH1: R64.1 R67.2 ; port RGB_LED_R
TIM4_CH2: R63.1 R66.2 ; port RGB_LED_G
TIM4_CH3: R62.1 R65.2 ; port RGB_LED_B
NetC39_2: C39.2 R54.2 U4.3(VDD)
NetC45_2: C45.2 H13.1 R55.2
NetC46_2: C46.2 C48.2 H12.3 J1.7 R61.2
NetC47_2: C47.2 J2.7 R60.1
NetD4_K: D4.K H11.2 R51.1 R52.1
NetD5_1: D5.1(K) R59.1
NetD5_2: D5.2(A) R56.2
NetD5_3: D5.3(K) R58.1
NetD5_4: D5.4(K) R57.1
NetQ1_D: Q1.D R59.2
NetQ1_G: Q1.G R62.2
NetQ2_D: Q2.D R58.2
NetQ2_G: Q2.G R63.2
NetQ3_D: Q3.D R57.2
NetQ3_G: Q3.G R64.2

Not connected (* = marked no-connect by the designer): MH1 1*; MH2 1*; U3 1(NC)* 2(NC)* 15(SDO/SA0)* 17(NC)* 18(NC)* 19(NC)* 20(NC)* 21(NC)* 22(NC)* 23(NC)* 24(NC)*

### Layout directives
net class DCMI: CAM_XCLK, DCMI_D0, DCMI_D1, DCMI_D2, DCMI_D3, DCMI_D4, DCMI_D5, DCMI_D6, DCMI_D7, DCMI_HSYNC, DCMI_PIXCLK, DCMI_VSYNC

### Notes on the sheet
- (near H8) SENSORS UART HEADER
- (near H9) SENSORS SPI HEADER
- (near H10) SENSORS I2C HEADER
- 4-20mA CURRENT MEASUREMENT
- MIKROBUS HEADER
- CAMERA HEADER
- I2C Address:
  Write - 0x42
  Read - 0x43
- Camera
- Mount Holes
- 5V only supplied when powering using USB-C or STLINK.
- XCLK connected to clock output of STM32 (RCC_MCO - PA8)
- RESET:
  Low - Reset mode
  High - Normal mode
- PWDN:
  Low - Normal Mode
  High - Power down mode
- QWIIC CONNECTOR
- ACCELEROMETER
- RGB LED
- (near R54) TEMPERATURE AND HUMIDITY SENSOR
- (near U4) Address = 0x44
- (near U3) Address = 0011001b = 0x19

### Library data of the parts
C36 = CAP0023-10: CAP CER 10NF 25V ±10% X7R 0402; Generic Allowed: Yes; Subtype: Ceramic
C37 C39 C45-C48 = CAP0068-11: as C2 on sheet STM_MCU
C38 = CAP0046-13: CAP CER 10UF 10V 20% X5R 0402; Subtype: Ceramic; Generic Allowed: Yes
D4 = DIO0071-3: TVS DIODE 3.3VWM 11.2VC SOD523; Voltage: 3.3V
D5 = DIO0045-2: LED, RGB, 624nm Red, 525nm Green, 470nm Blue LED Indication - Discrete 2V Red, 3.3V Green, 3.3V Blue 1206 (3216 Metric); Generic Allowed: Yes; Component Rating: Clear, 3.3V; Current: 20mA
H8 H10 = HDR0008-2: as H17 on sheet Power
H9 = HDR0114-1: Board Connector, 4 Contact(s), 1 Row(s), Male, Straight, Solder Terminal, 1x4
H11 = JCK0020-1: as H15 on sheet Power
H12 = HDR0118-1: QWIIC Connector, JST
H13 = HDR0112-1: Board Connector, 18 Contact(s), 2 Row(s), Female, Straight, 0.1 inch Pitch, Solder Terminal, Locking
J1 J2 = HDR0120-3: CONN RCPT 8POS 0.1 GOLD PCB
MH1 MH2 = PAD0009-2: MH NPTH 3.00mm DIA 2.75mm HOLE; Shape: Round
Q1-Q3 = TSR0015-4: MOSFET N-CH 60V 190MA TO236AB; Power: 265mW; Generic Allowed: No
R51 = RES0043-8: as R1 on sheet STM_MCU
R52 = RES0104-6: RES SMD 100R OHM ±0 .1% 1/16W 0603; Tolerance: 0 .1%; Generic Allowed: Yes
R53-R56 R60-R64 = RES0119-6: as R73 on sheet Power
R57 = RES0025-9: RES SMD 330R OHM ±1% 1/16W 0402; Generic Allowed: Yes
R58 = RES0042-9: RES SMD 1K OHM ±1% 1/16W 0402; Generic Allowed: Yes
R59 = RES0061-9: RES SMD 220R OHM ±1% 1/16W 0402; Generic Allowed: Yes
R65-R67 = RES0002-8: RES SMD 10K OHM ±1% 1/10W 0402; Generic Allowed: Yes
U3 = ICT0109-3: IC, Accelerometers High-performance ultra-low-power 3-axis accelerometer digital output for industr; Generic Allowed: No
U4 = ICT0108-3: IC, Humidity Temperature Sensor 0 ~ 100% RH I²C ±1.8% RH 6 s Surface Mount; Generic Allowed: No
U5 = MOD0006-3: MIKROBUS Module; Item_Number: MOD0012

## Sheet BLE_Module.SchDoc: BLE
size A4; ApprovedBy: Chad O'Neill; CheckedBy: Matthew Jay; Author: J. Garnier; DrawnBy: J. Garnier; Revision: 2.1; SheetNumber: 4; SheetTotal: 8
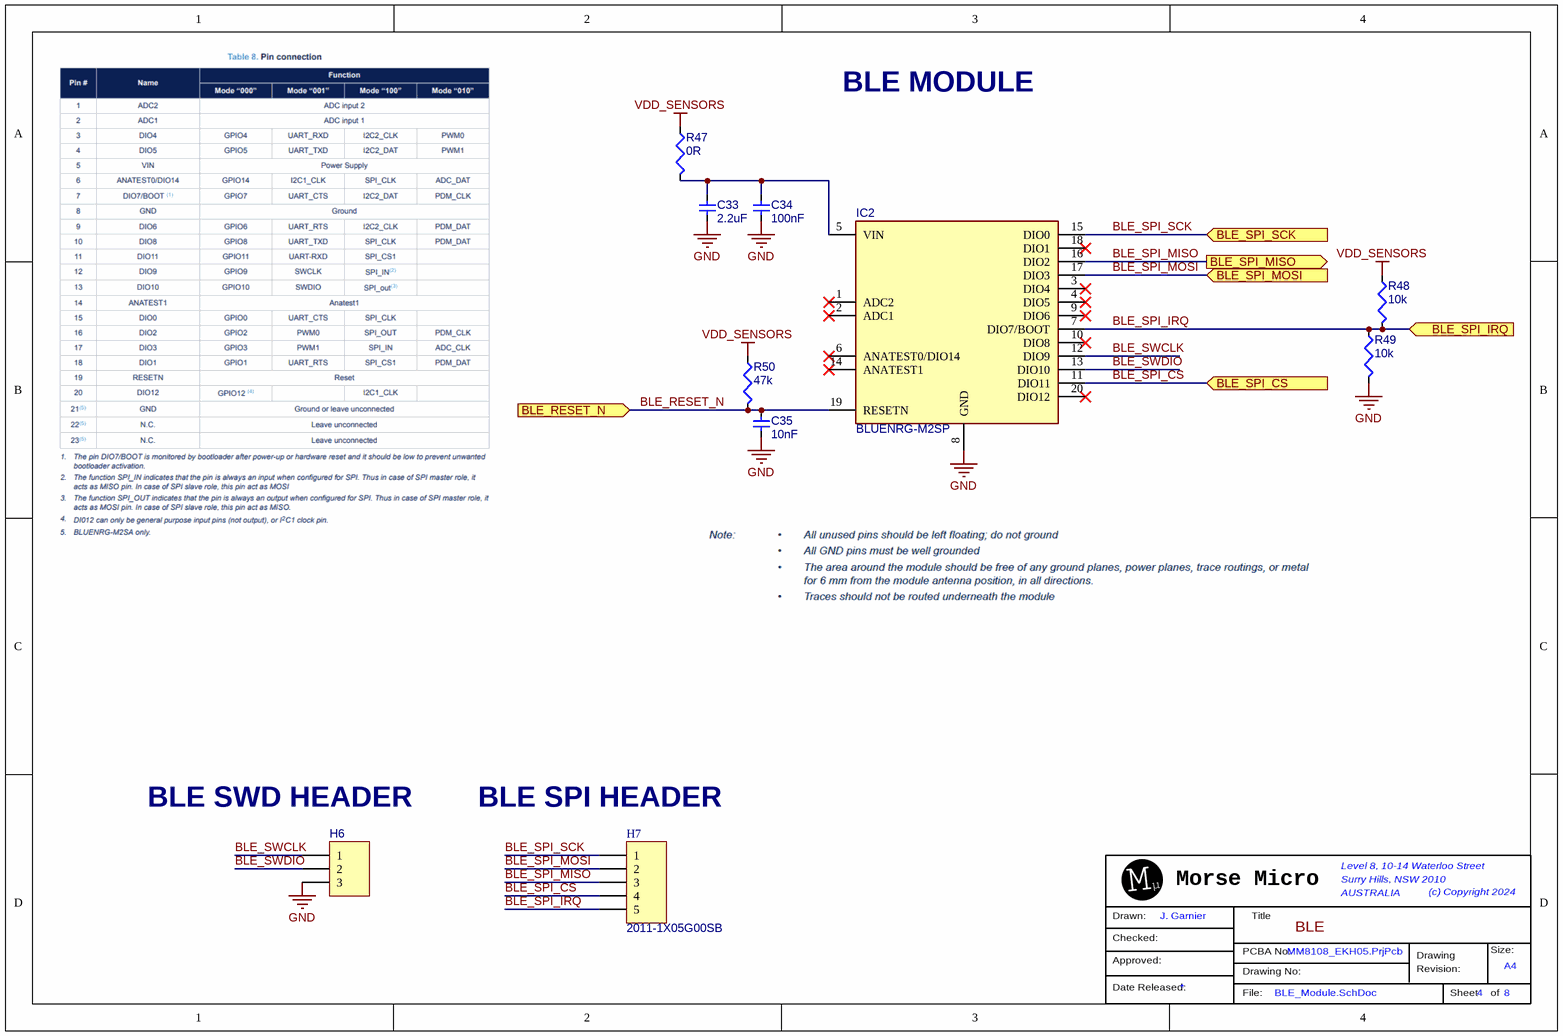
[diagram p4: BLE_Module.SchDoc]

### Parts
C33  value 2.2uF  [CAPC1005X06N]  (hidden comment: GRM155R61E225ME15D)
C34  value 100nF  [0402_cap]  (hidden comment: C1005X7R1H104K050BE)
C35  value 10nF  [0402_cap]  (hidden comment: GRM155R71E103KA01D)
H6  2011-1X03G00SB  [HDR1X3]  (value not drawn)
H7  2011-1X05G00SB  [HDR1X5 - Short Gold]
IC2  BLUENRG-M2SP  [BLUENRGM2SP]
R47  value 0R  [RESC1608X06N]  (hidden comment: RC0603JR-070RL)
R48  value 10k  [RESC1005X04N]  (hidden comment: RT0402BRD0710KL)
R49  value 10k  [RESC1005X04N]  (hidden comment: RT0402BRD0710KL)
R50  value 47k  [RESC1005X04N]  (hidden comment: MCR01MZPF4702)

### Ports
BLE_RESET_N (in, see Main[2C], STM_MCU[8B]), BLE_SPI_CS (in, see Main[2C], STM_MCU[5B]), BLE_SPI_IRQ (in, see Main[2C], STM_MCU[5B]), BLE_SPI_MISO (out, see Main[2C], STM_MCU[5C]), BLE_SPI_MOSI (in, see Main[2C], STM_MCU[5C]), BLE_SPI_SCK (in, see Main[2C], STM_MCU[5C])

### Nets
GND: C33.2 C34.1 C35.1 H6.3 IC2.8(GND) R49.2
VDD_SENSORS: R47.1 R48.1 R50.1
BLE_RESET_N: C35.2 IC2.19(RESETN) R50.2 ; port BLE_RESET_N
BLE_SPI_CS: H7.4 IC2.11(DIO11) ; port BLE_SPI_CS
BLE_SPI_IRQ: H7.5 IC2.7(DIO7/BOOT) R48.2 R49.1 ; port BLE_SPI_IRQ
BLE_SPI_MISO: H7.3 IC2.16(DIO2) ; port BLE_SPI_MISO
BLE_SPI_MOSI: H7.2 IC2.17(DIO3) ; port BLE_SPI_MOSI
BLE_SPI_SCK: H7.1 IC2.15(DIO0) ; port BLE_SPI_SCK
BLE_SWCLK: H6.1 IC2.12(DIO9)
BLE_SWDIO: H6.2 IC2.13(DIO10)
NetC33_1: C33.1 C34.2 IC2.5(VIN) R47.2

Not connected (* = marked no-connect by the designer): IC2 1(ADC2)* 2(ADC1)* 3(DIO4)* 4(DIO5)* 6(ANATEST0/DIO14)* 9(DIO6)* 10(DIO8)* 14(ANATEST1)* 18(DIO1)* 20(DIO12)*

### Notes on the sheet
- BLE MODULE
- (near H6) BLE SWD HEADER
- (near H7) BLE SPI HEADER

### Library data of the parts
C33 = CAP0055-10: as C12 on sheet STM_MCU
C34 = CAP0068-11: as C2 on sheet STM_MCU
C35 = CAP0023-11: CAP CER 10NF 25V ±10% X7R 0402; Generic Allowed: Yes; Subtype: Ceramic
H6 = HDR0008-2: as H17 on sheet Power
H7 = HDR0119-2: as H1 on sheet STM_MCU
IC2 = ICT0219-4: BLUENRGM2SP
R47 = RES0119-6: as R73 on sheet Power
R48 R49 = RES0244-8: RES SMD 10K OHM ±0.1% 1/16W 0402; Generic Allowed: Yes; Subtype: Thick Film
R50 = RES0086-8: RES SMD 47K OHM ±1% 1/16W 0402; Generic Allowed: Yes

## Sheet HaLow_Module.SchDoc: HaLow
size A3; ApprovedBy: Chad O'Neill; CheckedBy: Matthew Jay; Author: B. Attride; DrawnBy: B. Attride; Revision: 2.1; SheetNumber: 3; SheetTotal: 8
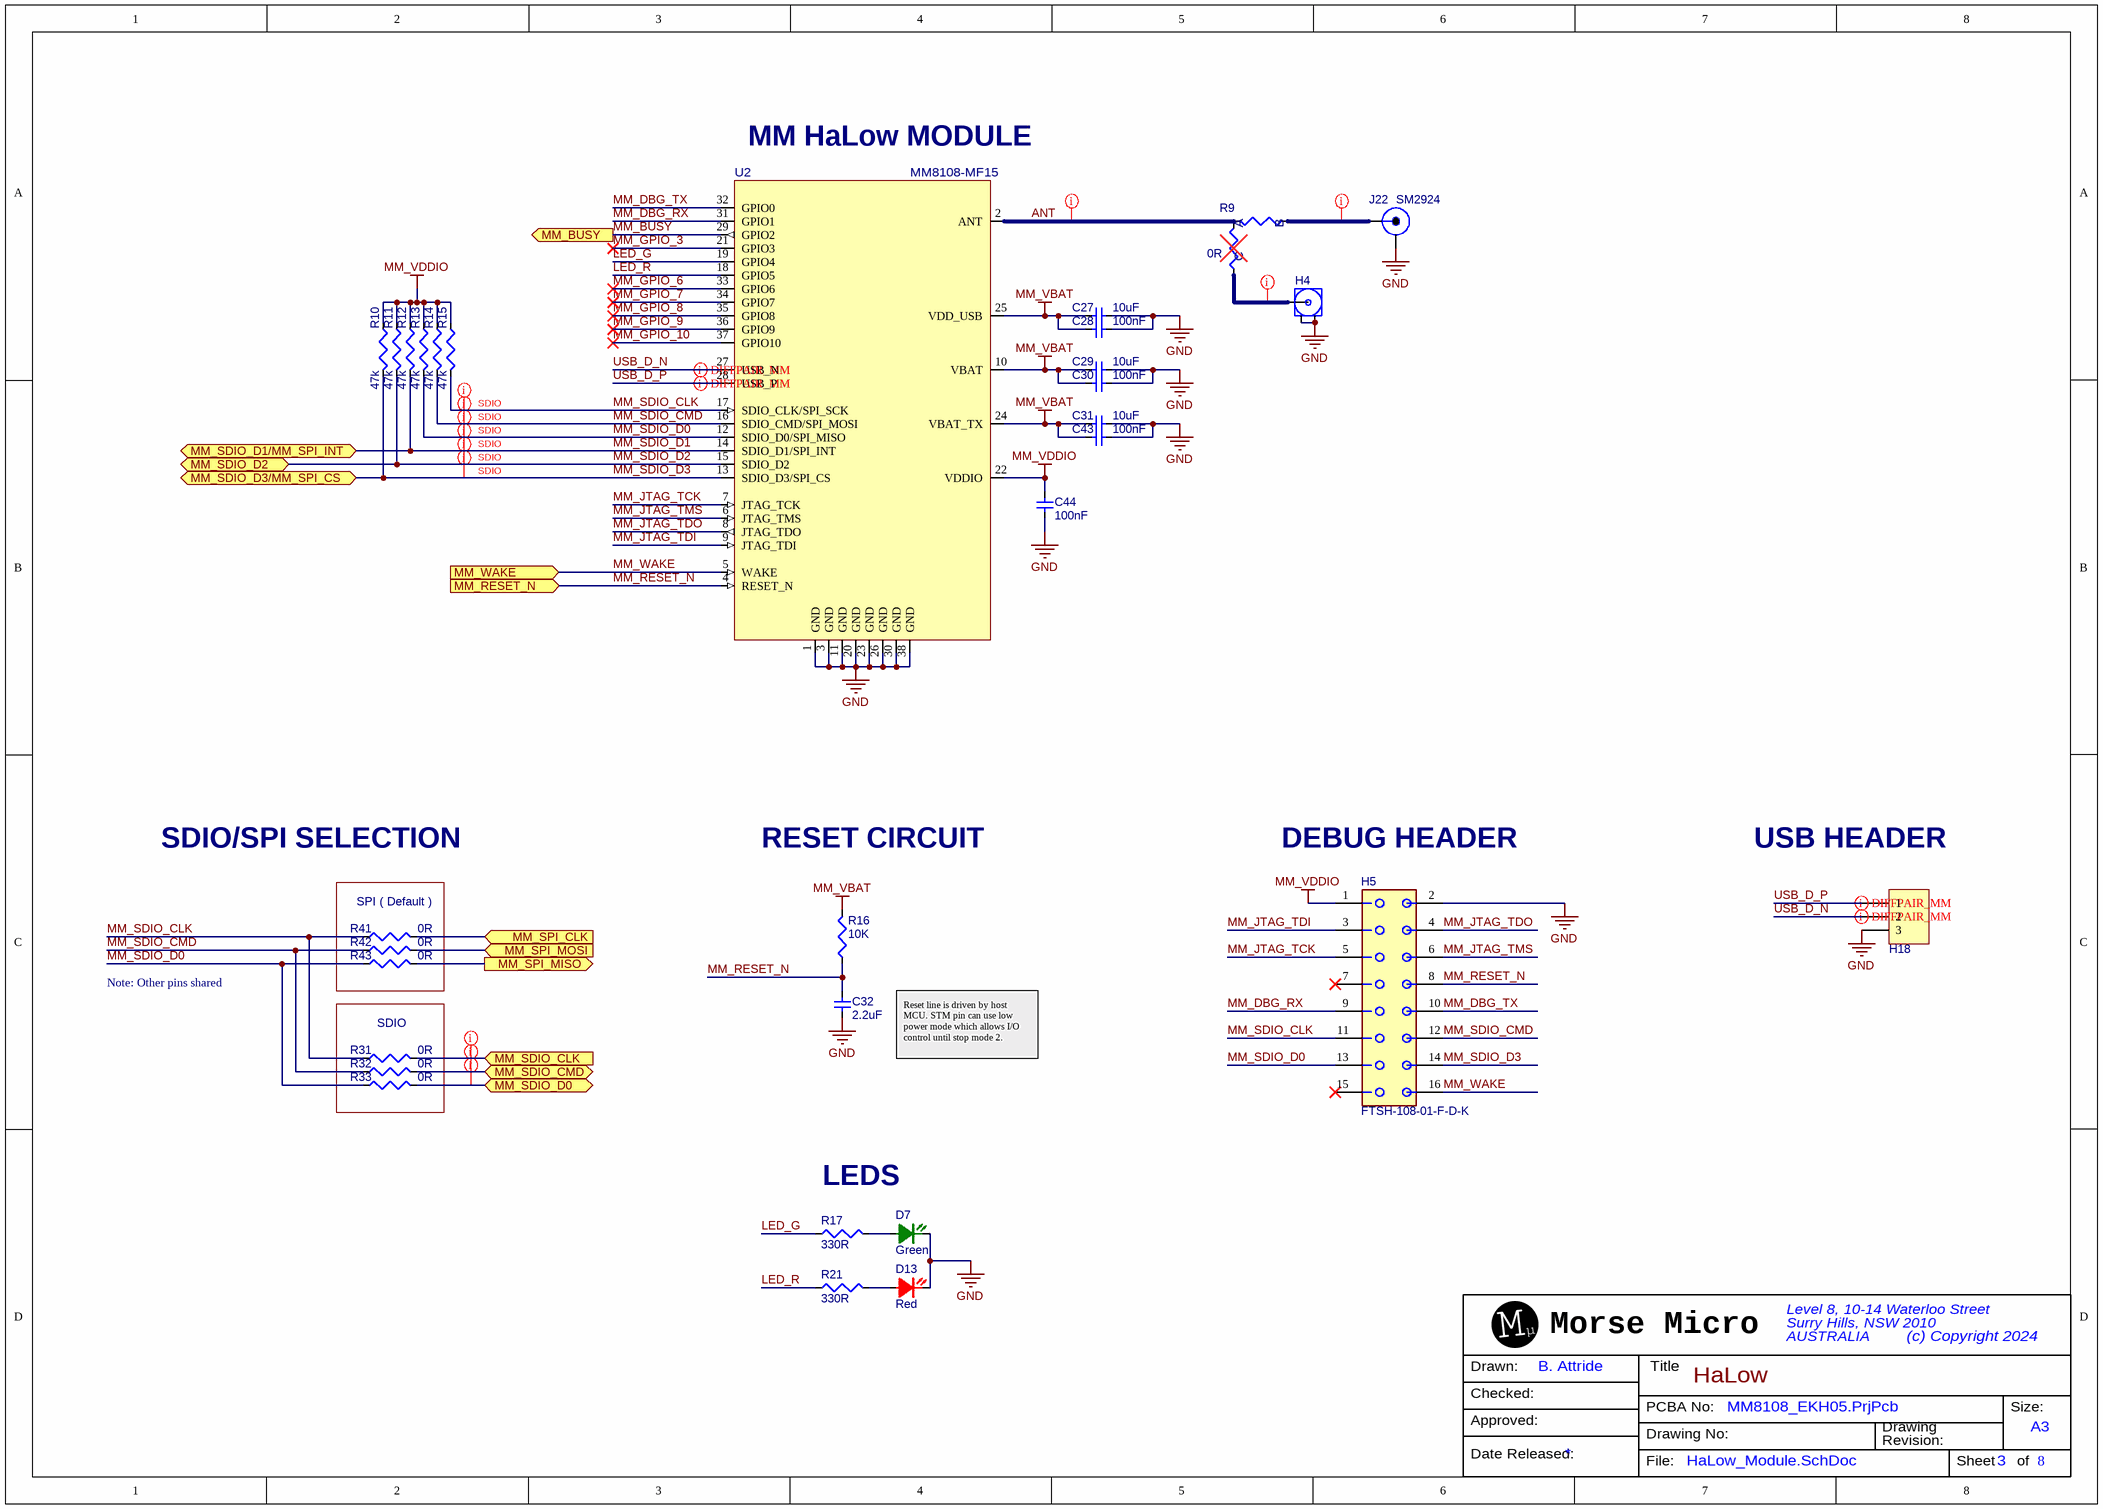
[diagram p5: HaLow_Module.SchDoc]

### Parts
C27  value 10uF  [CAPC1608X06L]  (hidden comment: GRM188R61E106MA73J)
C28  value 100nF  [0402_cap_rnd]  (hidden comment: C0402C104K8RACTU)
C29  value 10uF  [CAPC1608X06L]  (hidden comment: GRM188R61E106MA73J)
C30  value 100nF  [0402_cap_rnd]  (hidden comment: C0402C104K8RACTU)
C31  value 10uF  [CAPC1608X06L]  (hidden comment: GRM188R61E106MA73J)
C32  value 2.2uF  [CAPC1005X06N]  (hidden comment: GRM155R61E225ME15D)
C43  value 100nF  [0402_cap_rnd]  (hidden comment: C0402C104K8RACTU)
C44  value 100nF  [0402_cap_rnd]  (hidden comment: C0402C104K8RACTU)
D7  value Green  [LED_0402_GREEN]  (hidden comment: XZVGR68W-3)
D13  value Red  [LED_0402_RED]  (hidden comment: XZMDK68W-2)
H4  U.FL-R-SMT  [U_FL-R-SMT]  (value not drawn)
H5  FTSH-108-01-F-D-K  [FTSH_108_D_K]
H18  PHA1-S103-01GA  [HDR1X3]  (value not drawn)
J22  SM2924  [SM2924-Footprint-1]
R9  value 0R  [0603_RES_AB_RA]  (hidden comment: RES_AB)
R10  value 47k  [RESC1005X04N]  (hidden comment: MCR01MZPF4702)
R11  value 47k  [RESC1005X04N]  (hidden comment: MCR01MZPF4702)
R12  value 47k  [RESC1005X04N]  (hidden comment: MCR01MZPF4702)
R13  value 47k  [RESC1005X04N]  (hidden comment: MCR01MZPF4702)
R14  value 47k  [RESC1005X04N]  (hidden comment: MCR01MZPF4702)
R15  value 47k  [RESC1005X04N]  (hidden comment: MCR01MZPF4702)
R16  value 10K  [0201_res_rnd]  (hidden comment: ERJ-1GNF1002C)
R17  value 330R  [RESC1005X04N]  (hidden comment: RC0402FR-07330RL)
R21  value 330R  [RESC1005X04N]  (hidden comment: RC0402FR-07330RL)
R31  value 0R  [RESC1608X06N]  (hidden comment: RC0603JR-070RL)
R32  value 0R  [RESC1608X06N]  (hidden comment: RC0603JR-070RL)
R33  value 0R  [RESC1608X06N]  (hidden comment: RC0603JR-070RL)
R41  value 0R  [RESC1608X06N]  (hidden comment: RC0603JR-070RL)
R42  value 0R  [RESC1608X06N]  (hidden comment: RC0603JR-070RL)
R43  value 0R  [RESC1608X06N]  (hidden comment: RC0603JR-070RL)
U2  MM8108-MF15  [MF15]

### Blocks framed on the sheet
SPI ( Default ): R41-R43
SDIO: R31-R33

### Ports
MM_BUSY (out, see Main[2A], STM_MCU[5C]), MM_RESET_N (in, see Main[2A], STM_MCU[8C]), MM_SDIO_CLK (in, see Main[2A], STM_MCU[8C]), MM_SDIO_CMD (bidir, see Main[2A], STM_MCU[8C]), MM_SDIO_D0 (bidir, see Main[2A], STM_MCU[5C]), MM_SDIO_D1/MM_SPI_INT (bidir, see Main[2A], STM_MCU[4C]), MM_SDIO_D2 (bidir, see Main[2B], STM_MCU[5C]), MM_SDIO_D3/MM_SPI_CS (bidir, see Main[2B], STM_MCU[4C]), MM_SPI_CLK (in, see Main[2B], STM_MCU[8B]), MM_SPI_MISO (out, see Main[2B], STM_MCU[8B]), MM_SPI_MOSI (in, see Main[2B], STM_MCU[8B]), MM_WAKE (in, see Main[2A], STM_MCU[8B])

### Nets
GND: C27.2 C28.1 C29.2 C30.1 C31.2 C32.2 C43.1 C44.2 D7.K D13.K H4.2 H4.3 H5.2 H18.3 J22.2 U2.1(GND) U2.3(GND) U2.11(GND) U2.20(GND) U2.23(GND) U2.26(GND) U2.30(GND) U2.38(GND)
MM_VBAT: C27.1 C28.2 C29.1 C30.2 C31.1 C43.2 R16.2 U2.10(VBAT) U2.24(VBAT_TX) U2.25(VDD_USB)
MM_VDDIO: C44.1 H5.1 R10.1 R11.1 R12.1 R13.1 R14.1 R15.1 U2.22(VDDIO)
ANT: R9.A U2.2(ANT)
LED_G: R17.1 U2.19(GPIO4)
LED_R: R21.1 U2.18(GPIO5)
MM_BUSY: U2.29(GPIO2) ; port MM_BUSY
MM_DBG_RX: H5.9 U2.31(GPIO1)
MM_DBG_TX: H5.10 U2.32(GPIO0)
MM_GPIO_3: U2.21(GPIO3)
MM_GPIO_6: U2.33(GPIO6)
MM_GPIO_7: U2.34(GPIO7)
MM_GPIO_8: U2.35(GPIO8)
MM_GPIO_9: U2.36(GPIO9)
MM_GPIO_10: U2.37(GPIO10)
MM_JTAG_TCK: H5.5 U2.7(JTAG_TCK)
MM_JTAG_TDI: H5.3 U2.9(JTAG_TDI)
MM_JTAG_TDO: H5.4 U2.8(JTAG_TDO)
MM_JTAG_TMS: H5.6 U2.6(JTAG_TMS)
MM_RESET_N: C32.1 H5.8 R16.1 U2.4(RESET_N) ; port MM_RESET_N
MM_SDIO_CLK: H5.11 R15.2 R31.2 R41.1 U2.17(SDIO_CLK/SPI_SCK)
MM_SDIO_CMD: H5.12 R14.2 R32.2 R42.1 U2.16(SDIO_CMD/SPI_MOSI)
MM_SDIO_D0: H5.13 R13.2 R33.2 R43.1 U2.12(SDIO_D0/SPI_MISO)
MM_SDIO_D1: R12.2 U2.14(SDIO_D1/SPI_INT) ; port MM_SDIO_D1/MM_SPI_INT
MM_SDIO_D2: R11.2 U2.15(SDIO_D2) ; port MM_SDIO_D2
MM_SDIO_D3: H5.14 R10.2 U2.13(SDIO_D3/SPI_CS) ; port MM_SDIO_D3/MM_SPI_CS
MM_WAKE: H5.16 U2.5(WAKE) ; port MM_WAKE
SDMMC2_CLK: R31.1 ; port MM_SDIO_CLK
SDMMC2_CMD: R32.1 ; port MM_SDIO_CMD
SDMMC2_D0: R33.1 ; port MM_SDIO_D0
STM_SPI2_CLK: R41.2 ; port MM_SPI_CLK
STM_SPI2_MISO: R43.2 ; port MM_SPI_MISO
STM_SPI2_MOSI: R42.2 ; port MM_SPI_MOSI
USB_D_N: H18.2 U2.27(USB_N)
USB_D_P: H18.1 U2.28(USB_P)
NetD7_A: D7.A R17.2
NetD13_A: D13.A R21.2
NetH4_1: H4.1 R9.C
NetJ22_1: J22.1 R9.B

Not connected (* = marked no-connect by the designer): H5 7* 15*

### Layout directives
net class 50 OHMs: ANT, NetH4_1, NetJ22_1
net class SDIO_2: SDMMC2_CLK, SDMMC2_CMD, SDMMC2_D0
net class SDIO: MM_SDIO_CLK, MM_SDIO_CMD, MM_SDIO_D0, MM_SDIO_D1, MM_SDIO_D2, MM_SDIO_D3
differential pair; differential pair class DIFF_90: USB_D_N, USB_D_P

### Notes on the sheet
- MM HaLow MODULE
- SDIO/SPI SELECTION
- RESET CIRCUIT
- (near H5) DEBUG HEADER
- (near H18) USB HEADER
- Note: Other pins shared
- Reset line is driven by host MCU. STM pin can use low power mode which allows I/O control until stop mode 2.
- LEDS

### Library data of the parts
C27 C29 C31 = CAP0197-5: as C40 on sheet Power
C28 C30 C43 = CAP0025-11: CAP CER 100NF 10V ±10% X7R 0402; Generic Allowed: Yes; Subtype: Ceramic
C32 = CAP0055-10: as C12 on sheet STM_MCU
C44 = CAP0025-11: CAP CER 100NF 10V ±10% X7R 0402; Subtype: Ceramic; Generic Allowed: Yes
D7 = DIO0053-3: LED GREEN 0402 SMD; Generic Allowed: Yes; Voltage: 2.0V
D13 = DIO0052-2: LED RED 0402 SMD; Generic Allowed: Yes; Voltage: 1.95V
H4 = JCK0091-1: U.FL RF Connector; Generic Allowed: Yes
H5 = JCK0086-2: CONN,Vertical FTSH Series,0.05"16 Pins, Through Hole; Generic Allowed: No
H18 = HDR0122-1: Conn Straight Header 3x1 0.100" 3 POS; Generic Allowed: Yes
J22 = JCK0138-4: Wanshih RF SMD SMA connector with 2 GND pillars - Smaller Connector Barrel
R9 = RES0280: Ohms Jumper Chip Resistor 0603 ( 1608 Metric) - RES_AC; Manufacturer 1: Rohm; Manufacturer Part Number 1: MCR03EZPJ000; Generic Allowed: Yes; Power: 1/10W; Tolerance: 5%
R10-R15 = RES0086-8: as R50 on sheet BLE_Module
R16 = RES0019-10: RES SMD 10K OHM ±1% 1/20W 0201; Generic Allowed: Yes
R17 R21 = RES0025-8: as R75 on sheet Power
R31-R33 R41-R43 = RES0119-6: as R73 on sheet Power
U2 = MOD0024-3: Value: MM8108-MF15457

## Sheet Revision_History.SchDoc: Revision History
size A4; ApprovedBy: Chad O'Neill; CheckedBy: Matthew Jay; Author: J. Garnier; DrawnBy: J. Garnier; Revision: 2.1; SheetNumber: 8; SheetTotal: 8
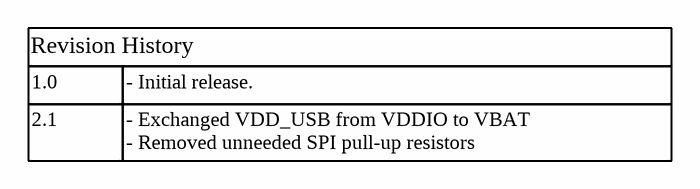
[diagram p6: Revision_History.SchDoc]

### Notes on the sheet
- Revision History
- 1.0
- - Initial release.
- 2.1
- - Exchanged VDD_USB from VDDIO to VBAT
  - Removed unneeded SPI pull-up resistors

## Sheet Mechanical.SchDoc: Mechanical
size A4; ApprovedBy: Chad O'Neill; CheckedBy: Matthew Jay; Revision: 2.1; SheetNumber: 7; SheetTotal: 8
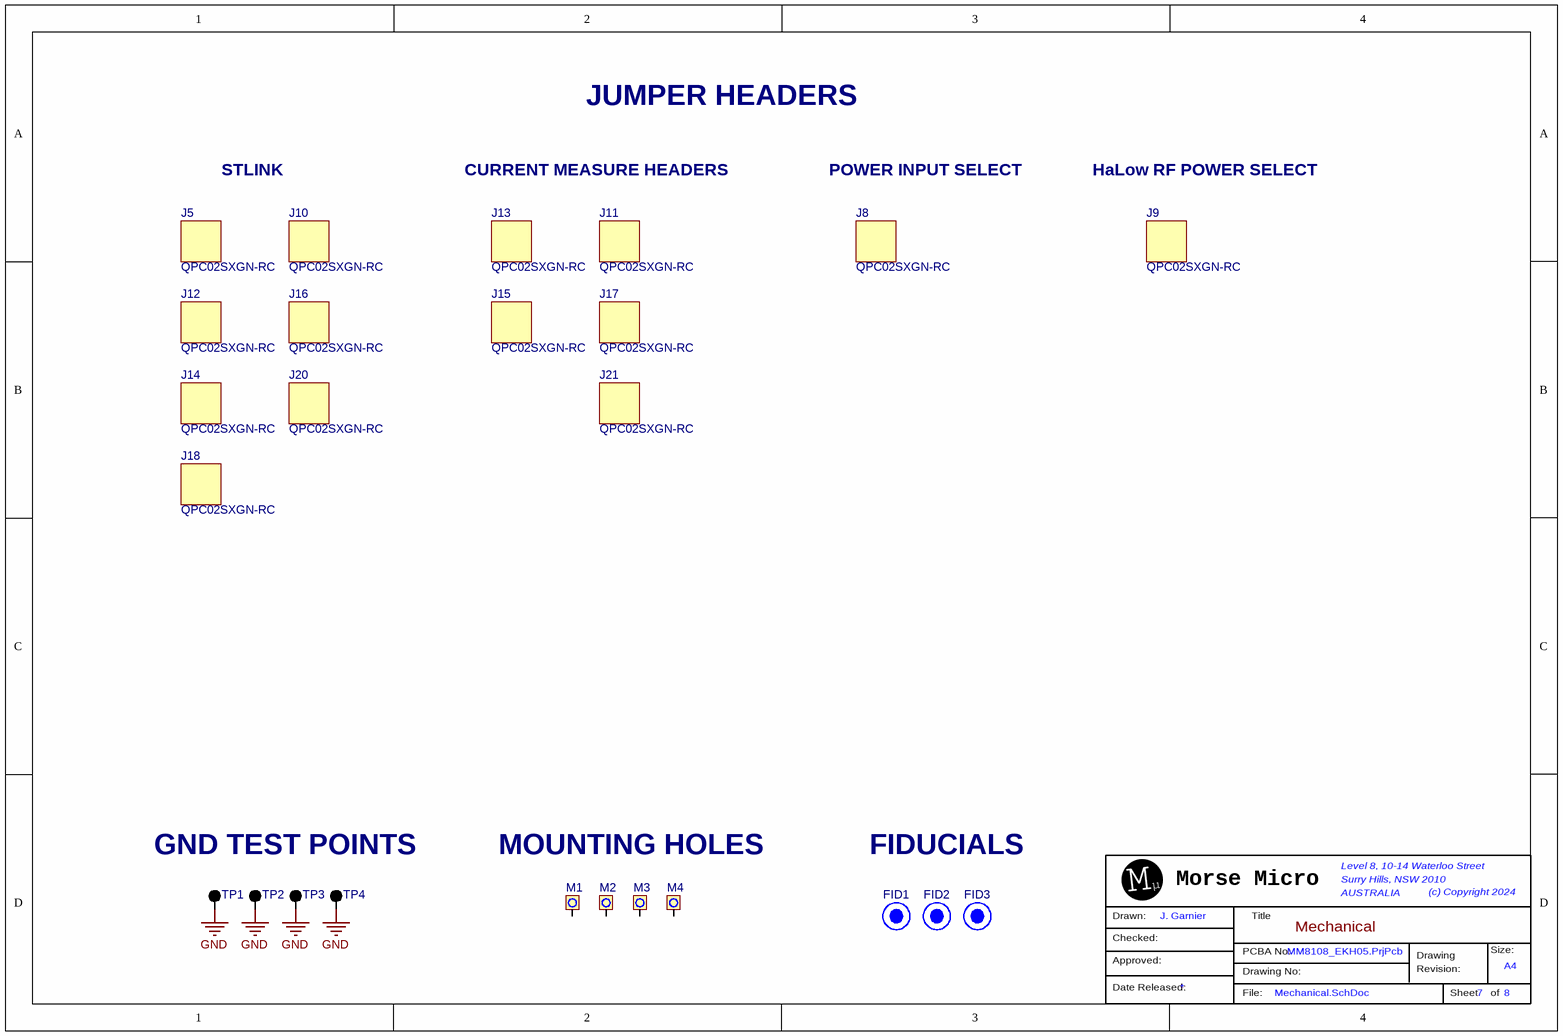
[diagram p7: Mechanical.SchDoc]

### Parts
FID1  PAD0002  [FIDUCIAL_1MM]  (value not drawn)  (no BOM)
FID2  PAD0002  [FIDUCIAL_1MM]  (value not drawn)  (no BOM)
FID3  PAD0002  [FIDUCIAL_1MM]  (value not drawn)  (no BOM)
J5  QPC02SXGN-RC  [FP-QPC02SXGN-RC-MFG]
J8  QPC02SXGN-RC  [FP-QPC02SXGN-RC-MFG]
J9  QPC02SXGN-RC  [FP-QPC02SXGN-RC-MFG]
J10  QPC02SXGN-RC  [FP-QPC02SXGN-RC-MFG]
J11  QPC02SXGN-RC  [FP-QPC02SXGN-RC-MFG]
J12  QPC02SXGN-RC  [FP-QPC02SXGN-RC-MFG]
J13  QPC02SXGN-RC  [FP-QPC02SXGN-RC-MFG]
J14  QPC02SXGN-RC  [FP-QPC02SXGN-RC-MFG]
J15  QPC02SXGN-RC  [FP-QPC02SXGN-RC-MFG]
J16  QPC02SXGN-RC  [FP-QPC02SXGN-RC-MFG]
J17  QPC02SXGN-RC  [FP-QPC02SXGN-RC-MFG]
J18  QPC02SXGN-RC  [FP-QPC02SXGN-RC-MFG]
J20  QPC02SXGN-RC  [FP-QPC02SXGN-RC-MFG]
J21  QPC02SXGN-RC  [FP-QPC02SXGN-RC-MFG]
M1  MH_300_275_NPTH  [MH_300_275_NPTH]  (value not drawn)  (no BOM)
M2  MH_300_275_NPTH  [MH_300_275_NPTH]  (value not drawn)  (no BOM)
M3  MH_300_275_NPTH  [MH_300_275_NPTH]  (value not drawn)  (no BOM)
M4  MH_300_275_NPTH  [MH_300_275_NPTH]  (value not drawn)  (no BOM)
TP1  TP-BLK  [FP-5001-MFG]  (value not drawn)
TP2  TP-BLK  [FP-5001-MFG]  (value not drawn)
TP3  TP-BLK  [FP-5001-MFG]  (value not drawn)
TP4  TP-BLK  [FP-5001-MFG]  (value not drawn)

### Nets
GND: TP1.1 TP2.1 TP3.1 TP4.1

Not connected (* = marked no-connect by the designer): M1 1; M2 1; M3 1; M4 1

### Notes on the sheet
- JUMPER HEADERS
- STLINK
- CURRENT MEASURE HEADERS
- POWER INPUT SELECT
- HaLow RF POWER SELECT
- GND TEST POINTS
- MOUNTING HOLES
- FIDUCIALS

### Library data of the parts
FID1-FID3 = PAD0002-2: 1mm Round Fiducial, 0.5mm Space
J5 J8-J18 J20 J21 = CMP-00006-6: Shunts/Jumper Connector; Manufacturer Series: QPC; Body Breadth: 0.097inch; Contact Pattern: RECTANGULAR; Body Depth: 0.235inch; Number Of Connectors: 1; Contact Style: SQ PIN-SKT; Body Length: 0.197inch; Polarization Key: POLARIZED HOUSING; Reliability: COMMERCIAL; Reference Standard: UL; Mounting Option 1: LOCKING; Rated Current (Signal): 3A; Mating Contact Pitch: 0.1inch
M1-M4 = PAD0031: MH NPTH 3.00mm DIA 2.75mm HOLE
TP1-TP4 = TPN0006-3: Test Point PCB, Black 0.040"D; Value: Black Color; Generic Allowed: Yes

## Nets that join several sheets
+5V: Power (8 pins), Sensors (R60.2)
GND: Power (32 pins), STM_MCU (46 pins), Sensors (32 pins), BLE_Module (6 pins), HaLow_Module (23 pins), Mechanical (TP1.1 TP2.1 TP3.1 TP4.1)
MM_VBAT: Power (H19.2), HaLow_Module (10 pins)
MM_VDDIO: Power (H3.2), HaLow_Module (9 pins)
VDD_MCU: Power (H24.2), STM_MCU (30 pins)
VDD_SENSORS: Power (H25.2), STM_MCU (C24.2 R82.1 R85.1 U1.8), Sensors (5 pins), BLE_Module (R47.1 R48.1 R50.1)
ACC_INT1: STM_MCU (IC1.28), Sensors (U3.7)
ACC_INT2: STM_MCU (IC1.29), Sensors (U3.3)
BLE_RESET_N: STM_MCU (IC1.83), BLE_Module (C35.2 IC2.19 R50.2)
BLE_SPI_CS: STM_MCU (IC1.77), BLE_Module (H7.4 IC2.11)
BLE_SPI_IRQ: STM_MCU (IC1.23), BLE_Module (H7.5 IC2.7 R48.2 R49.1)
BLE_SPI_MISO: STM_MCU (IC1.79), BLE_Module (H7.3 IC2.16)
BLE_SPI_MOSI: STM_MCU (IC1.80), BLE_Module (H7.2 IC2.17)
BLE_SPI_SCK: STM_MCU (IC1.78), BLE_Module (H7.1 IC2.15)
CAM_PWDN: STM_MCU (IC1.2), Sensors (H13.18)
CAM_RESET: STM_MCU (IC1.1), Sensors (H13.17)
CAM_XCLK: STM_MCU (IC1.67), Sensors (H13.8)
DBG_UART_STM_RX: Power (H16.11), STM_MCU (H2.2 IC1.15)
DBG_UART_STM_TX: Power (H16.13), STM_MCU (H2.1 IC1.16)
DCMI_D0: STM_MCU (IC1.63), Sensors (H13.16)
DCMI_D1: STM_MCU (IC1.64), Sensors (H13.15)
DCMI_D2: STM_MCU (IC1.65), Sensors (H13.14)
DCMI_D3: STM_MCU (IC1.66), Sensors (H13.13)
DCMI_D4: STM_MCU (IC1.3), Sensors (H13.12)
DCMI_D5: STM_MCU (IC1.92), Sensors (H13.11)
DCMI_D6: STM_MCU (IC1.4), Sensors (H13.10)
DCMI_D7: STM_MCU (IC1.5), Sensors (H13.9)
DCMI_HSYNC: STM_MCU (IC1.55), Sensors (H13.6)
DCMI_PIXCLK: STM_MCU (IC1.56), Sensors (H13.7)
DCMI_VSYNC: STM_MCU (IC1.93), Sensors (H13.5)
I2C_SCL: STM_MCU (IC1.95 R82.2), Sensors (6 pins)
I2C_SDA: STM_MCU (IC1.96 R85.2), Sensors (6 pins)
MIKRO_AN: STM_MCU (IC1.34), Sensors (J1.1)
MIKRO_INT: STM_MCU (IC1.37), Sensors (J2.2)
MIKRO_PWM: STM_MCU (IC1.38), Sensors (J2.1)
MIKRO_RST: STM_MCU (IC1.52), Sensors (J1.2)
MM_BUSY: STM_MCU (IC1.91), HaLow_Module (U2.29)
MM_RESET_N: STM_MCU (IC1.97), HaLow_Module (C32.1 H5.8 R16.1 U2.4)
MM_SDIO_D1: STM_MCU (IC1.54), HaLow_Module (R12.2 U2.14)
MM_SDIO_D2: STM_MCU (IC1.89 R3.2), HaLow_Module (R11.2 U2.15)
MM_SDIO_D3: STM_MCU (IC1.90), HaLow_Module (H5.14 R10.2 U2.13)
MM_WAKE: STM_MCU (IC1.81), HaLow_Module (H5.16 U2.5)
NetH16_5: Power (H16.5), STM_MCU (R3.1)
PD11: STM_MCU (IC1.58), Sensors (C36.1 R51.2)
SDMMC2_CLK: STM_MCU (IC1.87), HaLow_Module (R31.1)
SDMMC2_CMD: STM_MCU (IC1.88), HaLow_Module (R32.1)
SDMMC2_D0: STM_MCU (IC1.53), HaLow_Module (R33.1)
SENSORS_SPI_CLK: STM_MCU (IC1.41), Sensors (H9.1 J1.4)
SENSORS_SPI_CS: STM_MCU (IC1.40), Sensors (H9.4 J1.3)
SENSORS_SPI_MISO: STM_MCU (IC1.42), Sensors (H9.2 J1.5)
SENSORS_SPI_MOSI: STM_MCU (IC1.43), Sensors (H9.3 J1.6)
SENSORS_UART_RX: STM_MCU (IC1.44), Sensors (H8.1 J2.3)
SENSORS_UART_TX: STM_MCU (IC1.45), Sensors (H8.2 J2.4)
STM_NRST: Power (H16.9), STM_MCU (5 pins)
STM_SPI2_CLK: STM_MCU (IC1.82), HaLow_Module (R41.2)
STM_SPI2_MISO: STM_MCU (IC1.84), HaLow_Module (R43.2)
STM_SPI2_MOSI: STM_MCU (IC1.85), HaLow_Module (R42.2)
SWD_CLK: Power (H16.3), STM_MCU (IC1.76)
SWD_DIO: Power (H16.7), STM_MCU (IC1.72)
TIM4_CH1: STM_MCU (IC1.59), Sensors (R64.1 R67.2)
TIM4_CH2: STM_MCU (IC1.60), Sensors (R63.1 R66.2)
TIM4_CH3: STM_MCU (IC1.61), Sensors (R62.1 R65.2)
USBC_N: Power (D12.K J3.A7 J3.B7), STM_MCU (IC1.70)
USBC_P: Power (D11.K J3.A6 J3.B6), STM_MCU (IC1.71)

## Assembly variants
Default: not fitted D7 D8 D8 D9 D9 D10 D10 H5 H18 H? R3 R7 R10 R12 R13 R14 R16 R18 R18 R19 R19 R20 R25 R26 R31 R32 R33 R46 R48 R50 R78 R79 R80 R81 R83 R? R? U5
